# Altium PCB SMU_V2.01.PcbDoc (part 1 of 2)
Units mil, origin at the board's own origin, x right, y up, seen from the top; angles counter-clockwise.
Board outline 8661.42 x 7437.01 mil, 4 copper layers (Component Side, Ground Plane, Power Plane, Solder Side), stack 33.234 mil thick; 247 components, 163 nets, 805 pads, 762 vias.
Unrouted connection lines stored in the file: 6.
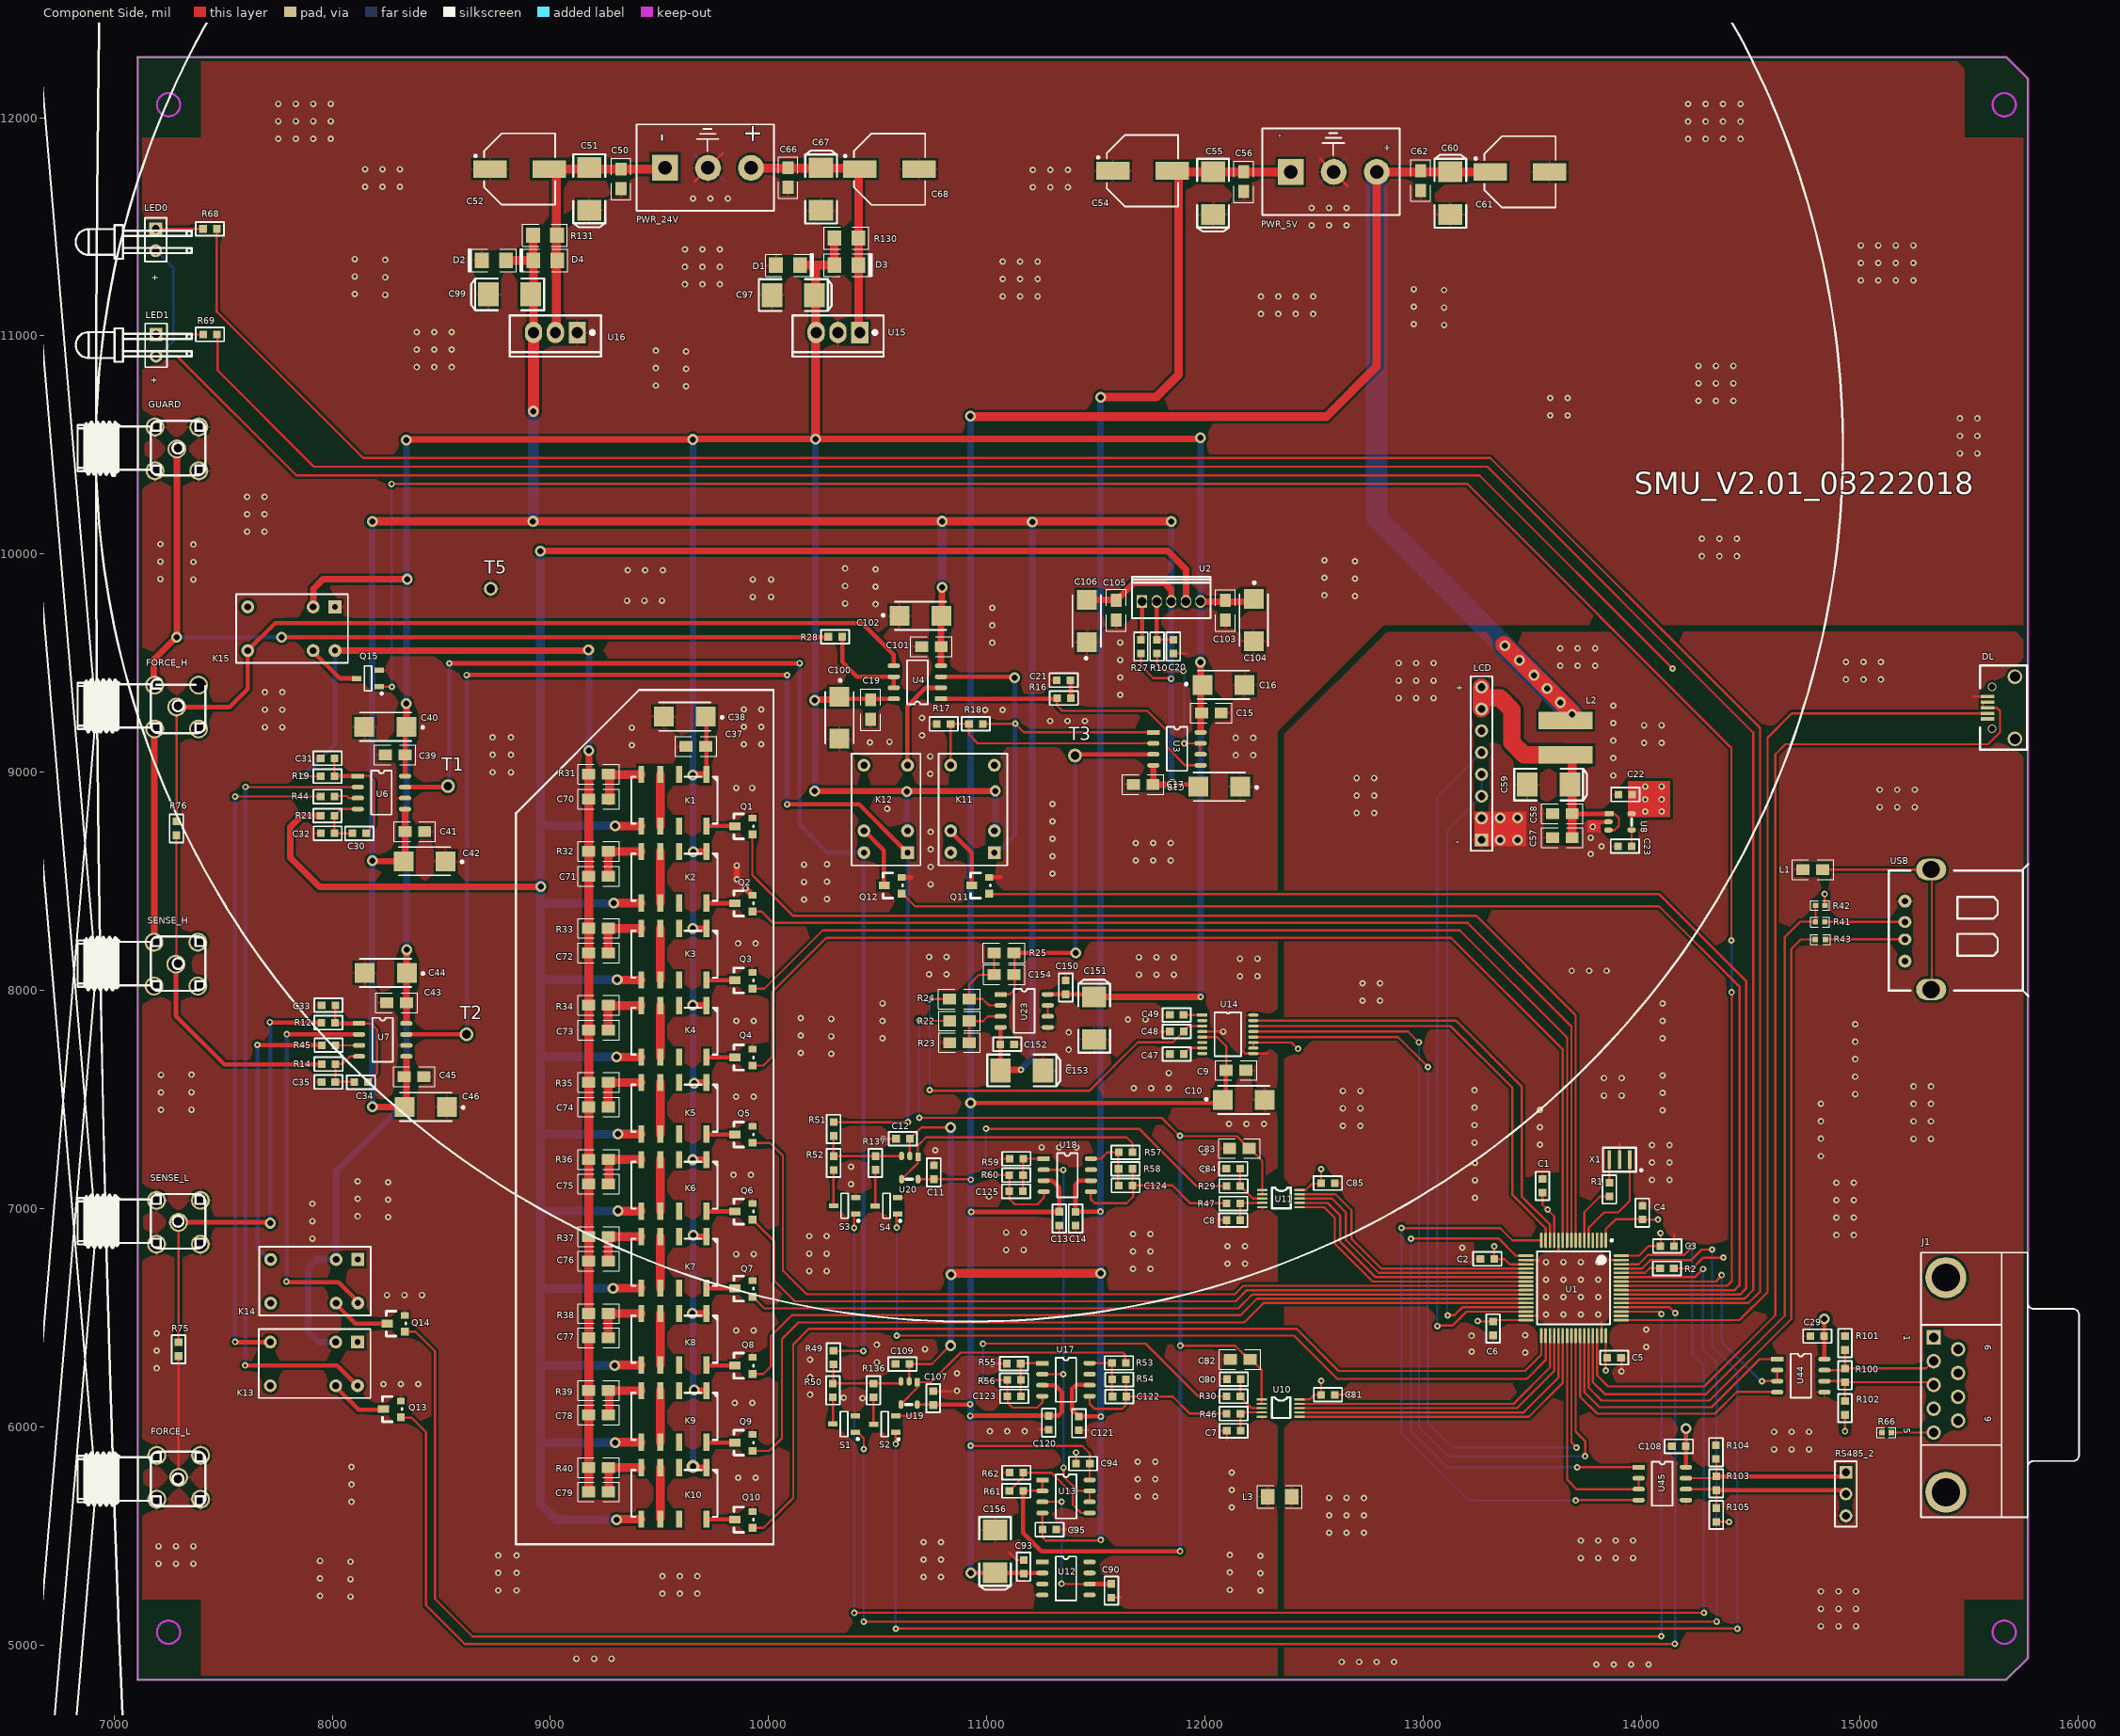
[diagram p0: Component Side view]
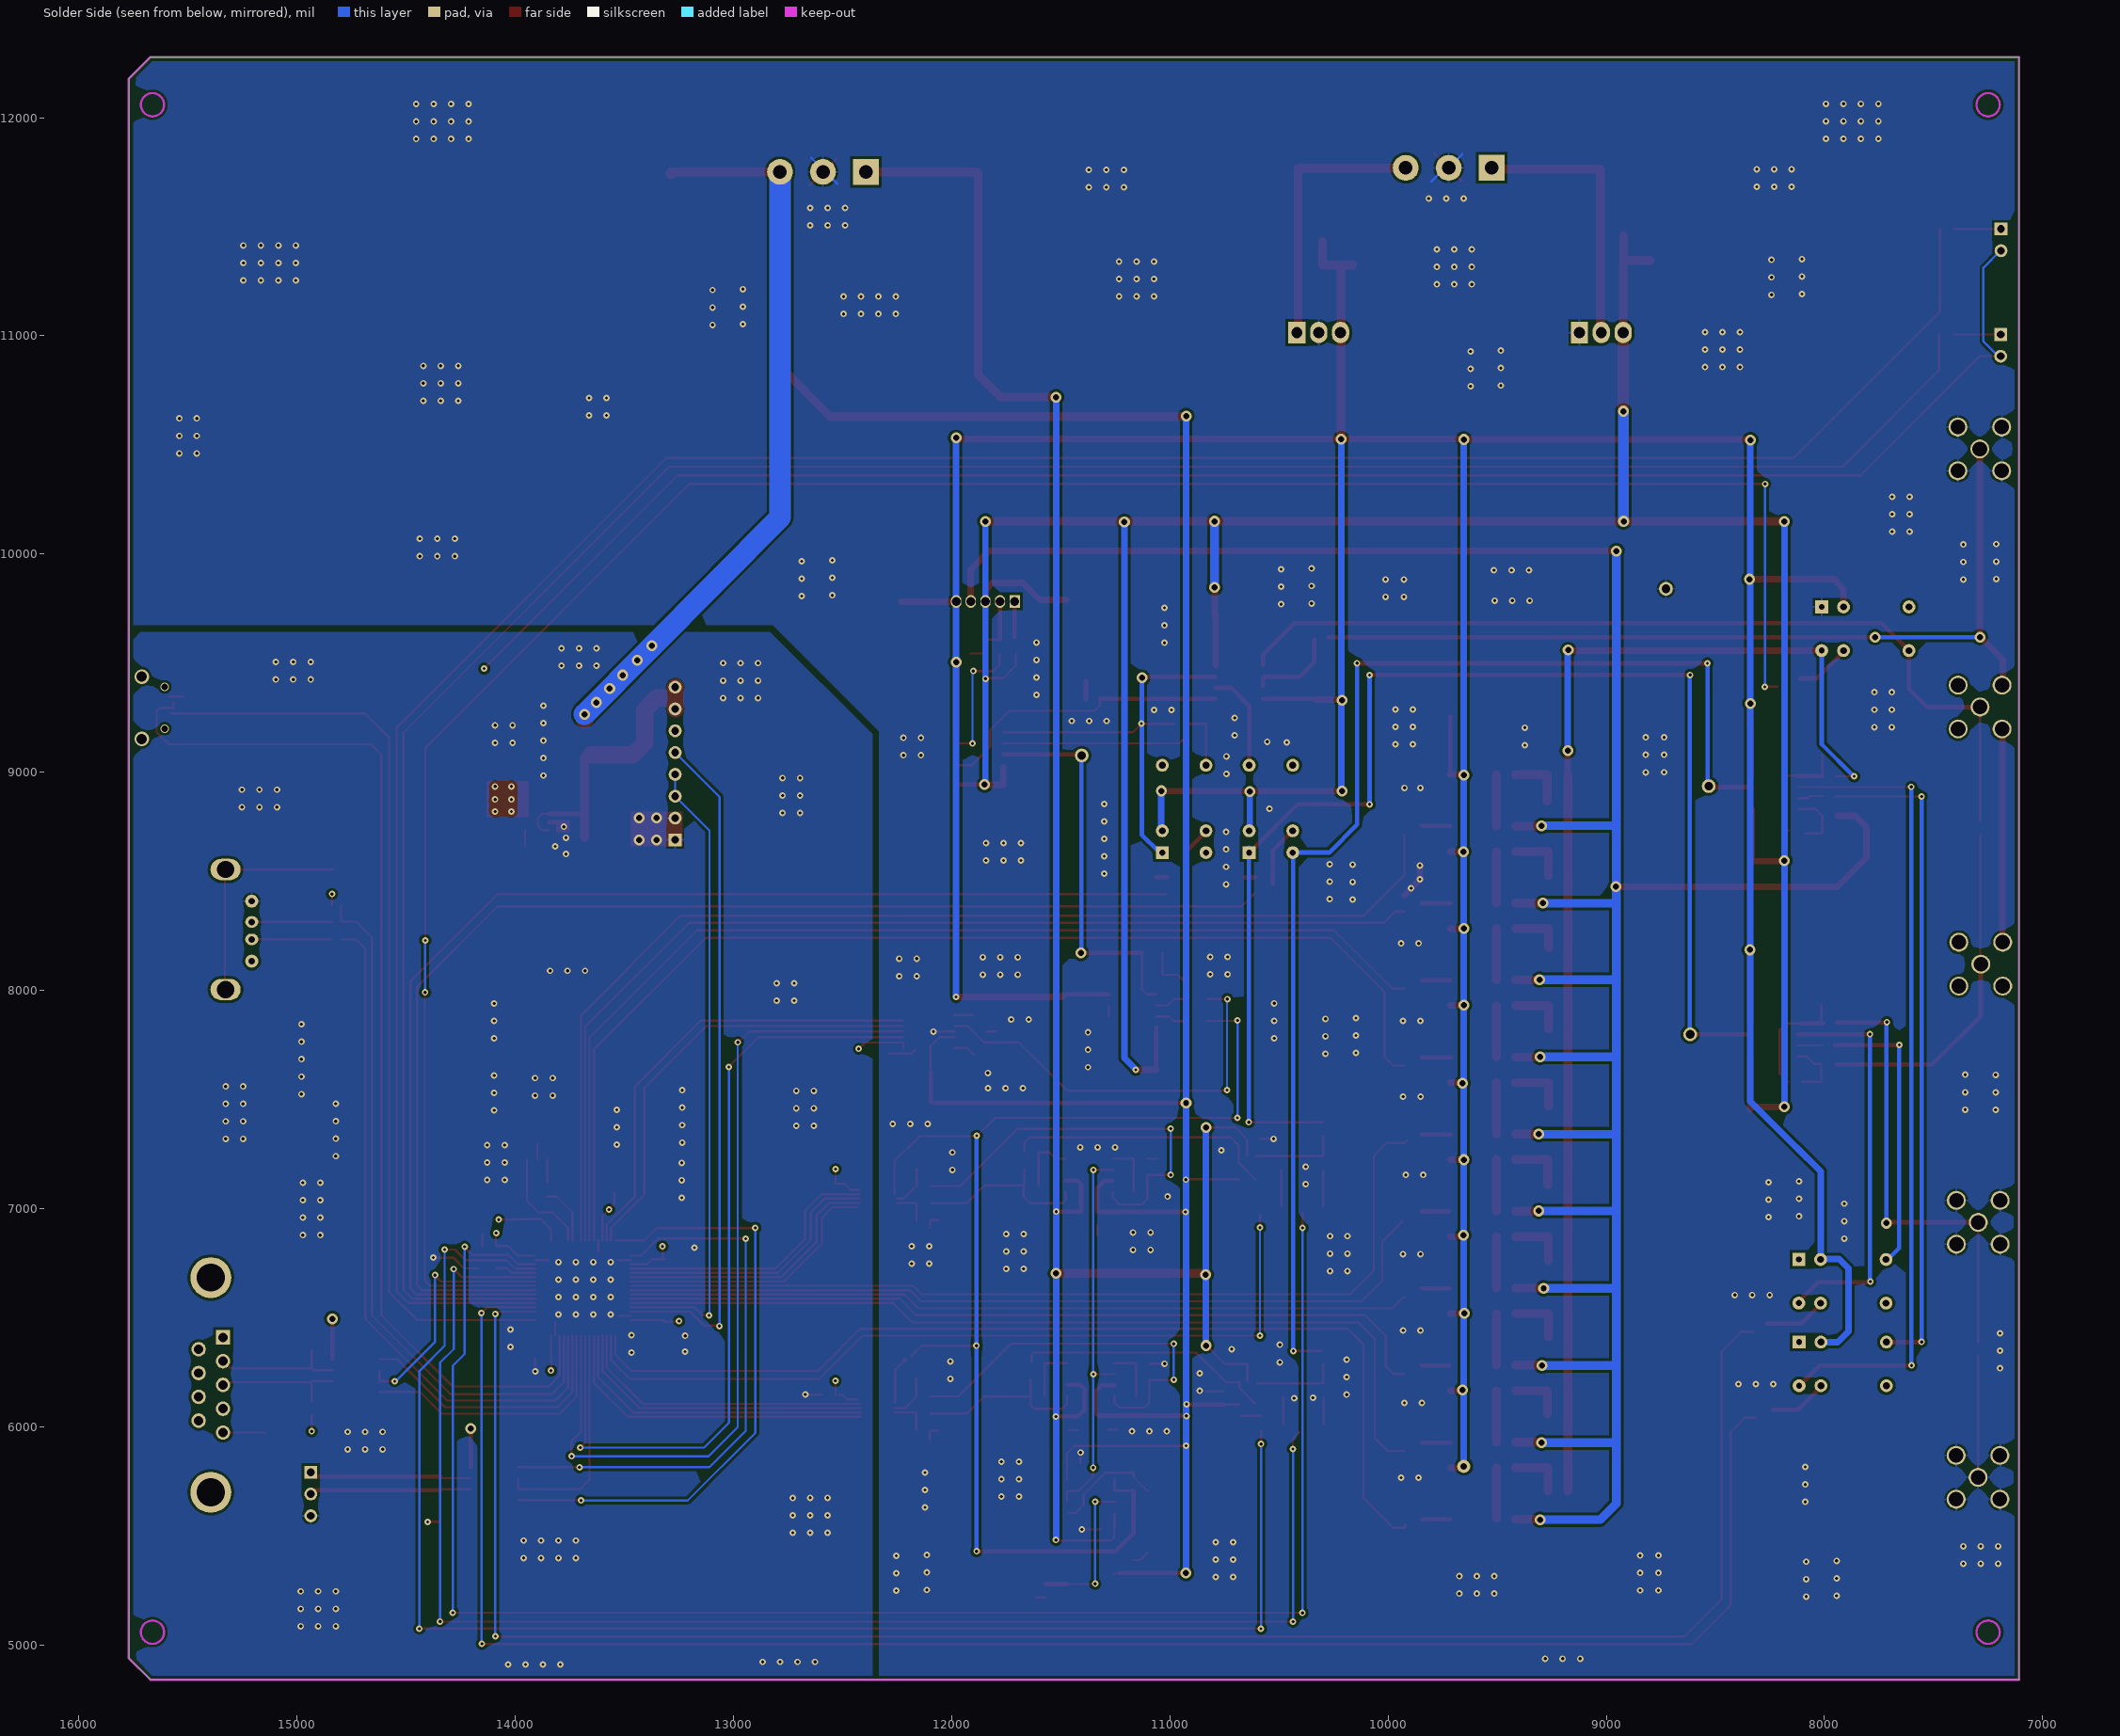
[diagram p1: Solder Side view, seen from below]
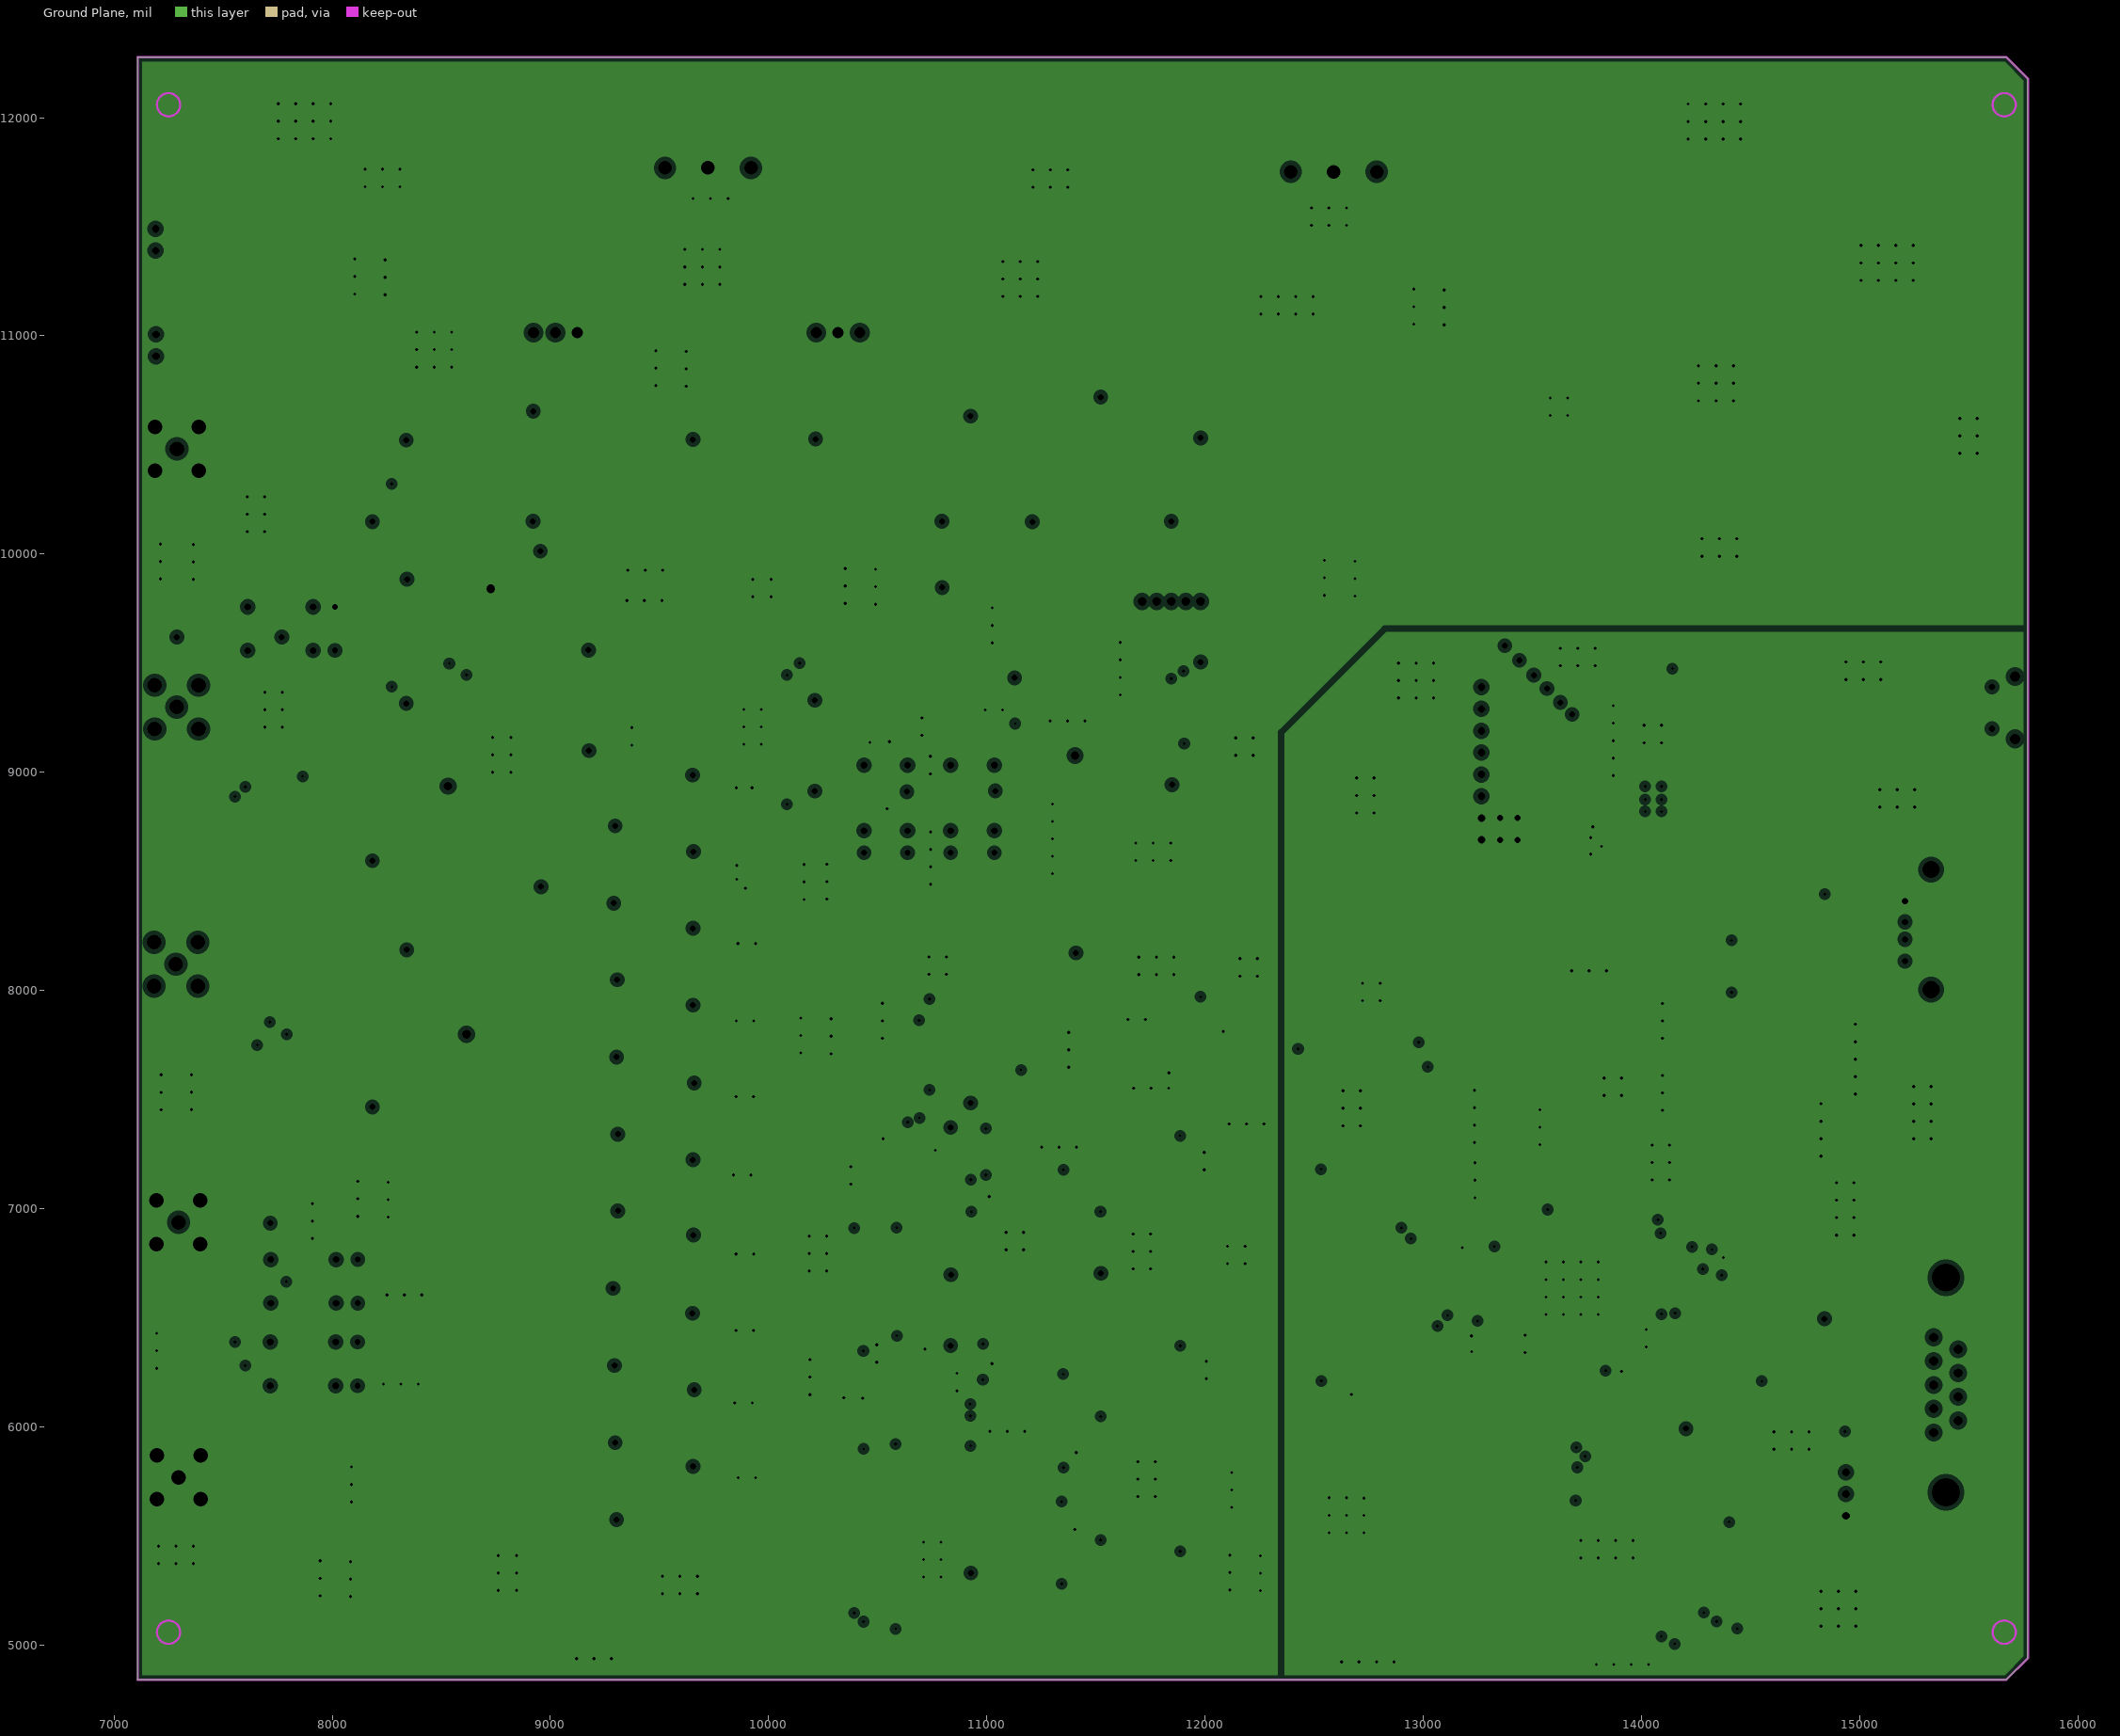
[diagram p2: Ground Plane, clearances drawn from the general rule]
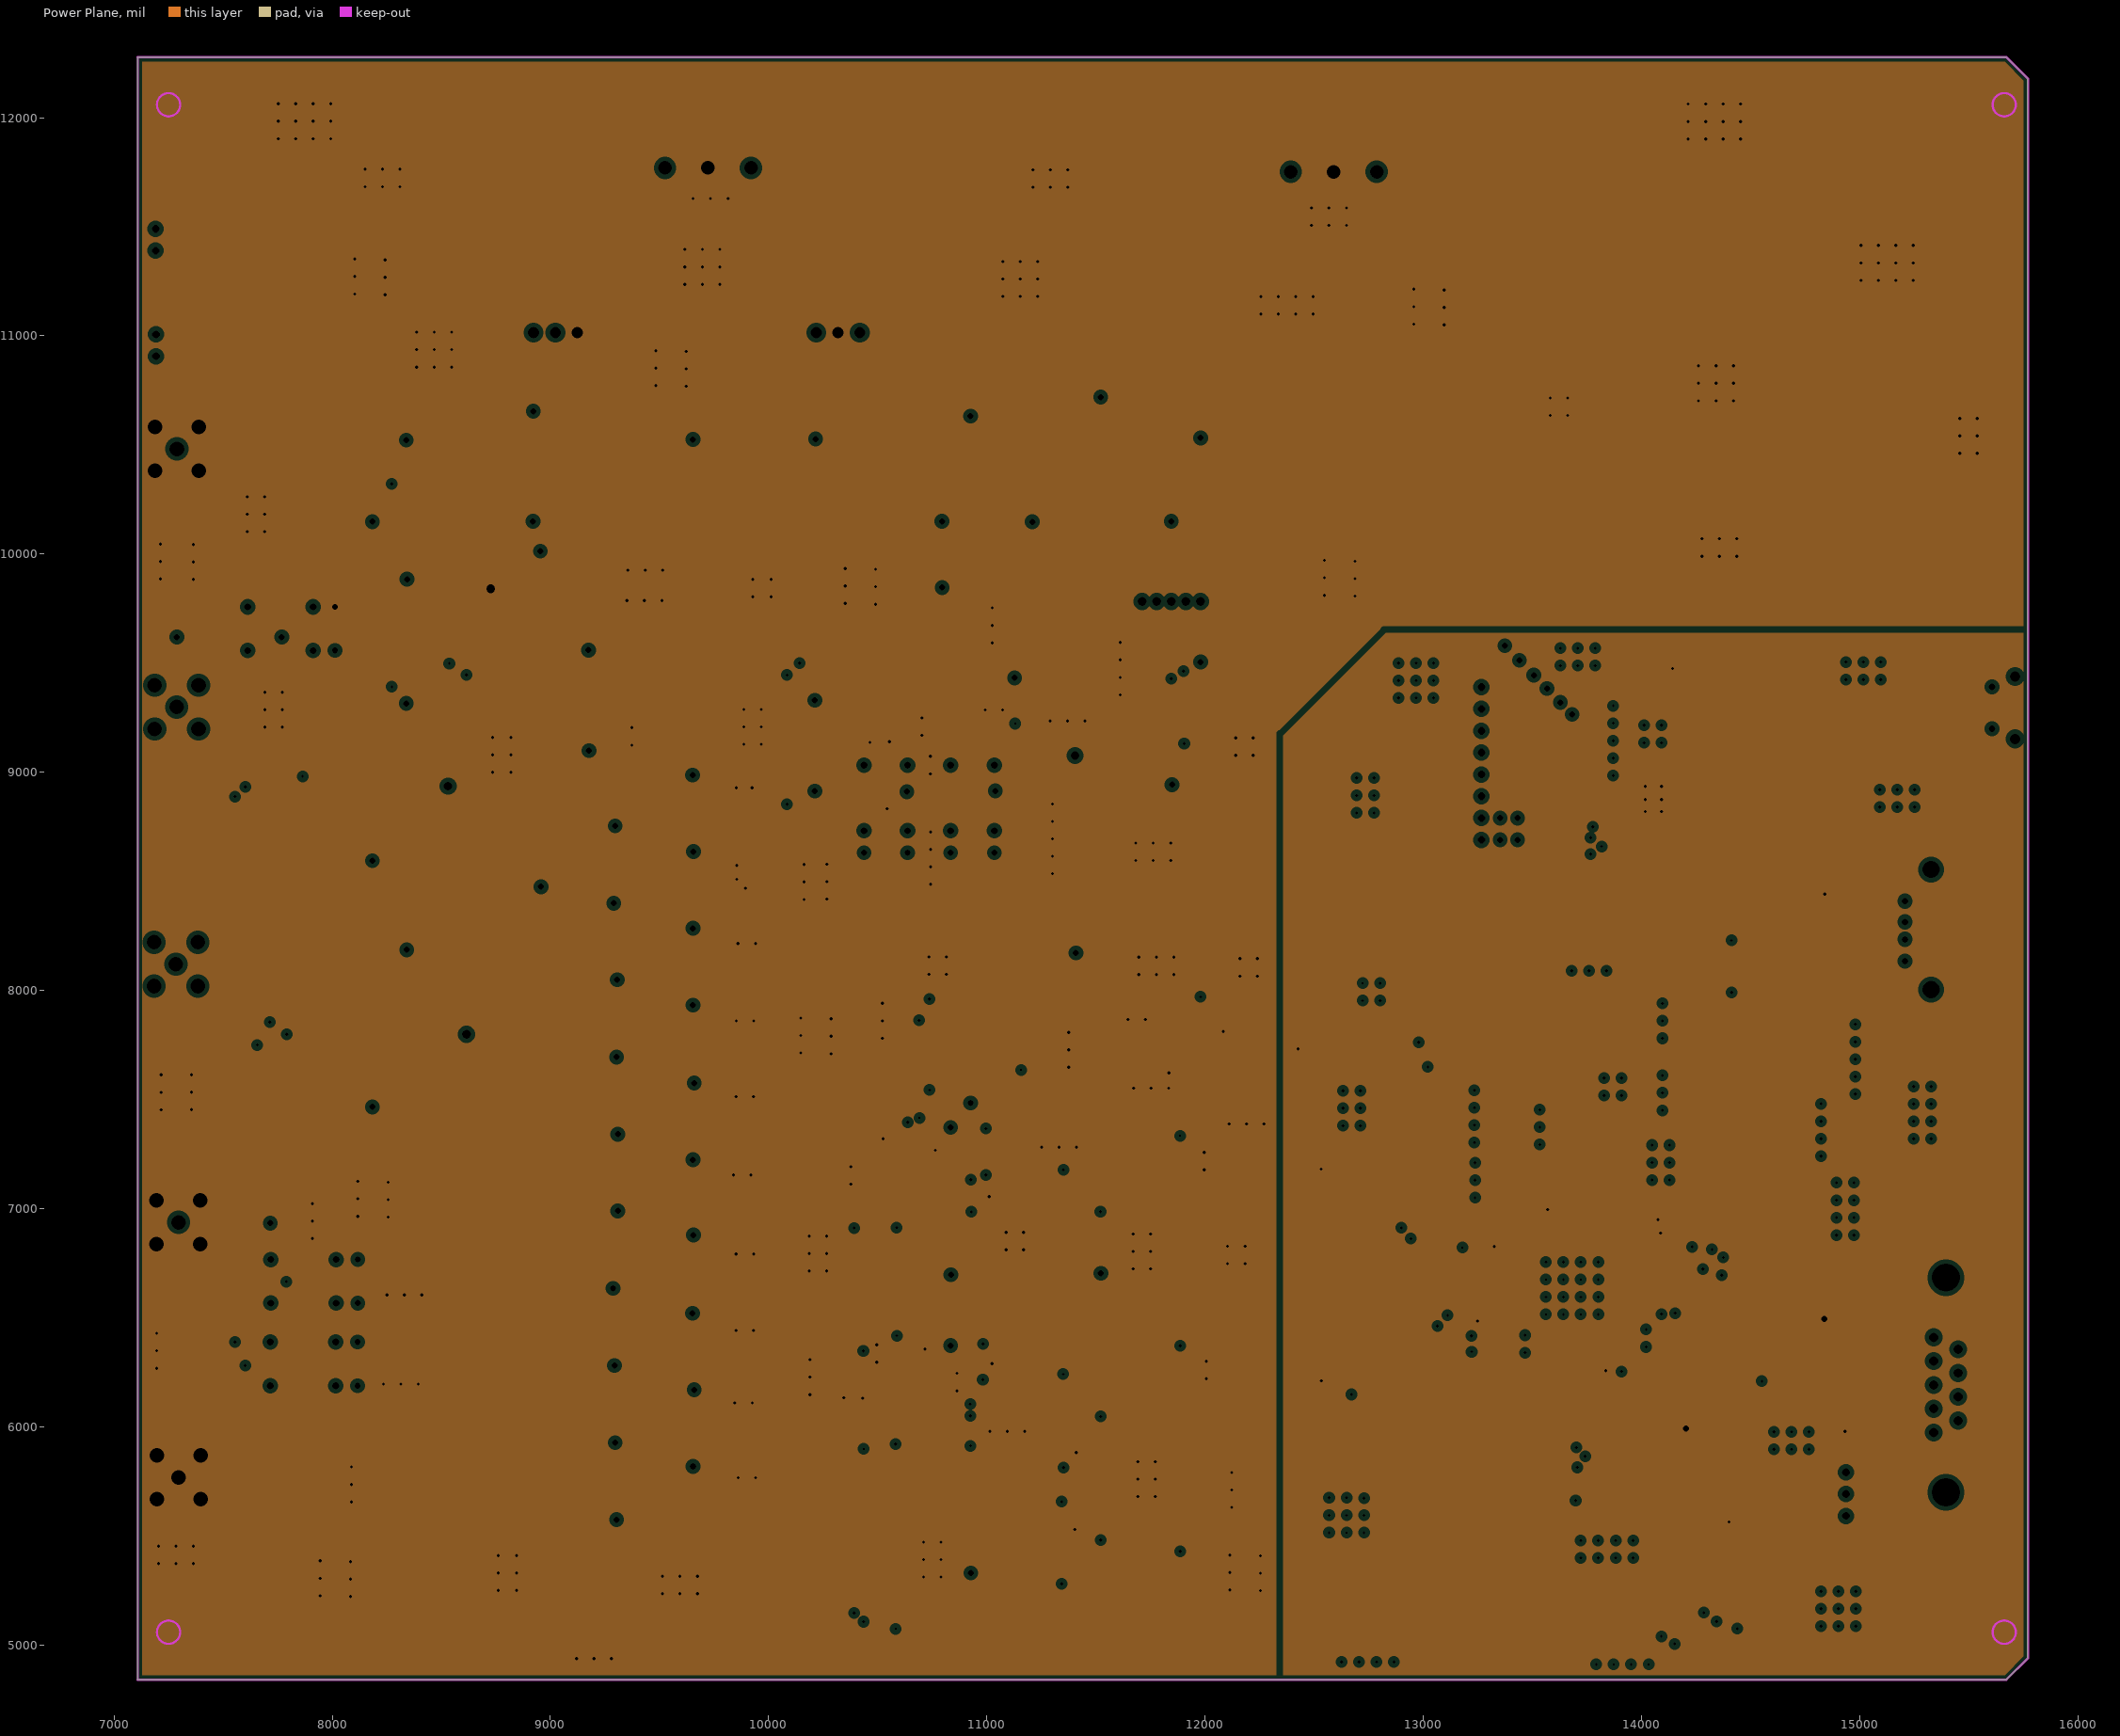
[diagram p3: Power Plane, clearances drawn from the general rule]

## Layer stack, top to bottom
Top Solder: solder mask 0.4, Solder Resist, Dk 3.5
Component Side: signal copper 1.4
Dielectric 1: core 12.6, FR-4, Dk 4.8
Ground Plane: plane copper 1.417, net (Multiple Nets)
Dielectric 3: prepreg 5, Dk 4.2
Power Plane: plane copper 1.417, net (Multiple Nets)
Dielectric 4: core 10, Dk 4.2
Solder Side: signal copper 1.4
Bottom Solder: solder mask 0.4, Solder Resist, Dk 3.5

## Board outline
7108.64,4840.98 15671.64,4840.98 15770.06,4939.41 15770.06,12179.56 15671.64,12277.99 7108.64,12277.99

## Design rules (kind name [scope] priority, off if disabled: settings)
Clearance [All] p1: gap=3
ComponentClearance [All] p1: gap=0 collisioncheckmode=3 verticalgap=0 showdistances=FALSE
MinimumSolderMaskSliver [All] p1: minsoldermaskwidth=0
PlaneClearance [All] p1: clearance=20
PlaneConnect PlaneConnect_GROUND [All] p1: planeconnectstyle=Relief reliefexpansion=20 reliefentries=4 reliefconductorwidth=10 reliefairgap=10
PlaneConnect "PlaneConnect _POWER" [All] p2: planeconnectstyle=Relief reliefexpansion=20 reliefentries=4 reliefconductorwidth=10 reliefairgap=10
PolygonConnect [IsVia] p1: connectstyle=Direct reliefconductorwidth=10 reliefentries=4 polygonreliefangle="90 Angle" airgapwidth=10
PolygonConnect PolygonConnect_1 [InNet('DGND')] p2: connectstyle=Relief reliefconductorwidth=10 reliefentries=4 polygonreliefangle="90 Angle" airgapwidth=10
PolygonConnect PolygonConnect_2 [InNet('AGND')] p3: connectstyle=Relief reliefconductorwidth=10 reliefentries=4 polygonreliefangle="90 Angle" airgapwidth=10
RoutingVias [All] p1: holewidth=28 width=50 viastyle="Through Hole" minholewidth=28 minwidth=50 maxholewidth=28 maxwidth=50
SilkToSilkClearance [All] p1: silktosilkclearance=0
SilkToSolderMaskClearance [IsPad] p1: minsilkscreentomaskgap=0 clearancetoexposedcopper=TRUE
SolderMaskExpansion [All] p1: expansion=4
UnpouredPolygon UnpouredPolygon_1 [All] p1:
Width [All] p1: maxlimit=100 minlimit=10 preferedwidth=10
23 further rules are at their usual default settings.

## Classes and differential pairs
component class Analog: C1 C2 C3 C4 C5 C6 C7 C8 C9 C10 C11 C12 C13 C14 C15 C16 C17 C18 C19 C20 C21 C22 C23 C29 C30 C31 C32 C33 C34 C35 C37 C38 C39 C40 C41 C42 C43 C44 C45 C46 C47 C48 C49 C57 C58 C59 C70 C71 C72 C73 C74 C75 C76 C77 C78 C79 C80 C81 C82 C83 C84 C85 C90 C93 C94 C95 C100 C101 C102 C103 C104 C105 C106 C107 C108 C109 C120 C121 C122 C123 C124 C125 C150 C151 C152 C153 C154 C156 DL FORCE_H FORCE_L GUARD J1 K1 K2 K3 K4 K5 K6 K7 K8 K9 K10 K11 K12 K13 K14 K15 L1 L3 LCD LED0 LED1 Q1 Q2 Q3 Q4 Q5 Q6 Q7 Q8 Q9 Q10 Q11 Q12 Q13 Q14 Q15 R1 R2 R10 R12 R14 R16 R17 R18 R19 R21 R22 R23 R24 R25 R27 R28 R29 R30 R31 R32 R33 R34 R35 R36 R37 R38 R39 R40 R41 R42 R43 R44 R45 R46 R47 R49 R50 R51 R52 R53 R54 R55 R56 R57 R58 R59 R60 R61 R62 R66 R68 R69 R75 R76 R100 R101 R102 R103 R104 R105 R136 R137 RS485_2 S1 S2 S3 S4 SENSE_H SENSE_L T1 T2 T3 T5 U1 U2 U3 U4 U6 U7 U8 U10 U11 U12 U13 U14 U17 U18 U19 U20 U23 U44 U45 USB X1
component class Power: C50 C51 C52 C54 C55 C56 C60 C61 C62 C66 C67 C68 C97 C99 D1 D2 D3 D4 L2 PWR_5V PWR_24V R130 R131 U15 U16

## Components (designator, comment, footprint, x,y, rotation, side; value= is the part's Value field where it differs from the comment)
C1 "100nF" 0603 13550.48,7043.53 r180 top
C2 "100nF" 0603 13354.54,6774.4 r270 top
C3 "100nF" 0603 14056.91,6824.38 r90 top
C4 "100nF" 0603 14008.06,6920.52 r180 top
C5 "100nF" 0603 13813.66,6312.96 r90 top
C6 "1uF" 0603 13315.34,6512.26 r0 top
C7 "22nF" 0603 12069.6,5978.17 r90 top
C8 "22nF" 0603 12068.37,6943.27 r90 top
C9 "100nF" 0805#1 12184.03,7609.44 r0 top
C10 "10uF" 6032_pol#1 12292.92,7453.09 r0 top
C11 "100nF" 0603 10760.95,7105.35 r180 top
C12 "100nF" 0603 10676.31,7324.54 r270 top
C13 "100nF" 0603 11327.81,7015.88 r0 top
C14 "100nF" 0603 11402.49,7015.82 r0 top
C15 "100nF" 0805#1 12070.49,9247.48 r0 top
C16 "10uF" 6032_pol#1 12200.77,9356.02 r0 top
C17 "100nF" 0805#1 11673.97,8969.84 r180 top
C18 "10uF" 6032_pol#1 11949.27,8978.82 r180 top
C19 "100nF" 0805#1 10441.9,9245.11 r270 top
C20 "1uF" 0603 11850.08,9637.47 r0 top
C21 "3.3nF" 0603 11290.55,9417.61 r90 top
C22 "1uF" 0603 13987.23,8902.48 r270 top
C23 "22nF" 0603 13985.05,8665.49 r270 top
C29 "100nF" 0603 14866.88,6420.31 r270 top
C30 "10nF" 0603 8063.17,8716 r90 top
C31 "1nF" 0603 8039.71,9068.37 r270 top
C32 "1nF" 0603 7918.07,8716.26 r90 top
C33 "1nF" 0603 8043.66,7936.76 r270 top
C34 "10nF" 0603 8070.53,7575.3 r90 top
C35 "1nF" 0603 7921.06,7576.63 r90 top
C37 "100nF" 0805#1 9624.82,9143.09 r180 top
C38 "10uF" 6032_pol#1 9499.21,9300.12 r180 top
C39 "100nF" 0805#2 8333.18,9079.96 r180 top
C40 "10uF" 6032_pol#1 8127.6,9253.9 r180 top
C41 "100nF" 0805#2 8333.18,8727.7 r0 top
C42 "10uF" 6032_pol#1 8307.8,8637.61 r180 top
C43 "100nF" 0805#1 8252.87,7968.98 r180 top
C44 "10uF" 6032_pol#1 8128.97,8125.71 r180 top
C45 "100nF" 0805#1 8417.16,7580.34 r0 top
C46 "10uF" 6032_pol#1 8312.48,7511.95 r180 top
C47 "100nF" 0603 11808.82,7704.57 r90 top
C48 "100nF" 0603 11808.73,7807.87 r90 top
C49 "100nF" 0603 11808.57,7883.63 r90 top
C50 "100nF" 0805#2 9323.53,11674.48 r90 top
C51 "10uF" 6032_POL 9179.33,11676.39 r270 top
C52 "47uF" cap_pol_8*10.2#1 8858.53,11764.48 r0 top
C54 "47uF,50V" cap_pol_8*10.2#1 11712.82,11756.73 r0 top
C55 "10uF" 6032_POL 12037.82,11656.73 r270 top
C56 "1uF" 0805#2 12177.82,11751.73 r270 top
C57 "100nF" 0805#2 13681.88,8700.31 r180 top
C58 "1uF" 0805#2 13681.88,8810.31 r180 top
C59 "10uF" 6032_POL 13571.88,8945.31 r0 top
C60 "10uF" 6032_POL 13122.82,11651.73 r90 top
C61 "47uF,50V" cap_pol_8*10.2#1 13442.82,11751.73 r0 top
C62 "1uF" 0805#2 12987.82,11756.73 r270 top
C66 "100nF" 0805#2 10088.88,11680.76 r90 top
C67 "10uF" 6032_pol#2 10238.3,11670.99 r90 top
C68 "47uF" cap_pol_8*10.2#2 10553.42,11764.23 r90 top
C70 "10uF" 0805#1 9178.42,8902.04 r180 top
C71 "1uF" 0805#1 9178.42,8549.31 r180 top
C72 "100nF" 0805#1 9178.42,8196.58 r180 top
C73 "10nF" 0805#1 9178.42,7843.86 r180 top
C74 "1nF" 0805#1 9178.42,7491.13 r180 top
C75 "100pF" 0805#1 9178.42,7138.4 r180 top
C76 "10pF" 0805#1 9178.42,6785.67 r180 top
C77 "1pF" 0805#2 9265.42,6407.94 r180 top
C78 "NULL" 0805#1 9178.42,6080.22 r180 top
C79 "NULL" 0805#1 9178.42,5727.49 r180 top
C80 "22nF" 0603 12070.8,6214.57 r90 top
C81 "100nF" 0603 12501.95,6142.99 r90 top
C82 "10uF" 0805#2 12115.37,6309.11 r0 top
C83 "10uF" 0805#2 12112.28,7276.4 r0 top
C84 "22nF" 0603 12190.12,7187.39 r270 top
C85 "100nF" 0603 12501.73,7112.73 r90 top
C90 "100nF" 0603 11566.02,5310.6 r0 top
C93 "100nF" 0603 11164.02,5419.82 r0 top
C94 "100nF" 0603 11501.73,5835.91 r270 top
C95 "100nF" 0603 11225.8,5525.27 r90 top
C97 "4.7uF" 6032_pol#2 10110.36,11188.68 r0 top
C99 "4.7uF" 6032_pol#2 8814.93,11188.34 r180 top
C100 "10uF" 6032_pol#1 10279.34,9133.91 r270 top
C101 "100nF" 0805#1 10703.53,9600.98 r180 top
C102 "10uF" 6032_pol#1 10811.76,9671.85 r0 top
C103 "100nF" 0805#1 12068.6,9700.4 r270 top
C104 "10uF" 6032_pol#1 12177.51,9581.71 r270 top
C105 "100nF" 0805#1 11568.47,9700.93 r270 top
C106 "10uF" 6032_pol#1 11502.57,9809.31 r90 top
C107 "100nF" 0603 10758.22,6070.24 r180 top
C108 "100nF" 0603 14231.88,5915.31 r270 top
C109 "100nF" 0603 10674.38,6292.32 r270 top
C120 "100nF" 0603 11279.16,6080.54 r0 top
C121 "100nF" 0603 11417.42,6077.73 r0 top
C122 "100pF" 0603 11545.94,6134.74 r90 top
C123 "100pF" 0603 11186.51,6144.43 r270 top
C124 "100pF" 0603 11574.9,7102.1 r90 top
C125 "100pF" 0603 11195.13,7083.88 r270 top
C150 "100nF" 0603 11365.84,7952.81 r180 top
C151 "10uF" 6032_pol#2 11490.03,7870.86 r90 top
C152 "100nF" 0603 11032.3,7749.28 r90 top
C153 "10uF" 6032_pol#2 11157.57,7635.09 r0 top
C154 "100pF" 0805#2 11124.08,8072.24 r180 top
C156 "10uF" 6032_pol#2 11039.23,5431.95 r270 top
D1 "1N4007" 1N4007_M7 10085.74,11310.46 r0 top
D2 "1N4007" 1N4007_M7 8742.68,11359.59 r180 top
D3 "Diode 1N4007" 1N4007_M7 10353.38,11310.75 r0 top
D4 "Diode 1N4007" 1N4007_M7 8979.22,11359.85 r180 top
DL "USB_5pin" USBmicro_B 15691,9305.31 r270 top
FORCE_H "SMB" SMA 7186.47,9399.39 r0 top
FORCE_L "SMB" SMA 7195.73,5869.31 r0 top
GUARD "SMB" SMA 7187.68,10582.57 r0 top
J1 "USART" DSUB1.385-2H9 15768.88,6192.26 r270 top
K1 "AXICOM IM" AXICOM_IM06 9590.6,8865 r180 top
K2 "AXICOM IM" AXICOM_IM06 9590.6,8512.03 r180 top
K3 "AXICOM IM" AXICOM_IM06 9590.6,8159.06 r180 top
K4 "AXICOM IM" AXICOM_IM06 9590.6,7806.09 r180 top
K5 "AXICOM IM" AXICOM_IM06 9590.6,7453.12 r180 top
K6 "AXICOM IM" AXICOM_IM06 9590.6,7100.15 r180 top
K7 "AXICOM IM" AXICOM_IM06 9590.6,6747.18 r180 top
K8 "AXICOM IM" AXICOM_IM06 9590.6,6394.2 r180 top
K9 "AXICOM IM" AXICOM_IM06 9590.6,6041.23 r180 top
K10 "AXICOM IM" AXICOM_IM06 9590.6,5688.26 r180 top
K11 "Relay" Relay_OMRON5V 11034.46,8632.05 r180 top
K12 "Relay" Relay_OMRON5V 10636.55,8632.05 r180 top
K13 "Relay" Relay_OMRON5V 8116.11,6388.63 r270 top
K14 "Relay" Relay_OMRON5V 8117.56,6767.3 r270 top
K15 "Relay" Relay_OMRON5V 8012.65,9757.88 r270 top
L1 "10uH" 0805#2 14740.19,8554.29 r0 top
L2 "10uH" 8040 13651.88,9080.31 r0 top
L3 "10uH" 1206 12286.48,5679.69 r0 top
LCD "Header 8" HDR1X8 13266.88,8690.31 r90 top
LED0 "Header 2" HDR1X2 7190.85,11490.63 r270 top
LED1 "Header 2" HDR1X2 7192.45,11006.75 r270 top
PWR_5V "Header 3" PWR_3T 12392.82,11751.73 r90 top
PWR_24V "Header 3" PWR_3T 9525.2,11770.04 r90 top
Q1 "NUD3112" SOT_23 9925.06,8722.04 r0 top
Q2 "NUD3112" SOT_23 9925.06,8368.95 r0 top
Q3 "NUD3112" SOT_23 9925.06,8015.87 r0 top
Q4 "NUD3112" SOT_23 9925.06,7662.79 r0 top
Q5 "NUD3112" SOT_23 9925.06,7309.7 r0 top
Q6 "NUD3112" SOT_23 9925.06,6956.62 r0 top
Q7 "NUD3112" SOT_23 9925.06,6603.54 r0 top
Q8 "NUD3112" SOT_23 9925.06,6250.45 r0 top
Q9 "NUD3112" SOT_23 9925.06,5897.37 r0 top
Q10 "NUD3112" SOT_23 9925.06,5544.29 r0 top
Q11 "NUD3112" SOT_23 11010.38,8451.12 r0 top
Q12 "NUD3112" SOT_23 10608.7,8450.55 r0 top
Q13 "NUD3112" SOT_23 8314.41,6051.05 r0 top
Q14 "NUD3112" SOT_23 8331.76,6443.14 r0 top
Q15 "NUD3112" SOT23 8162.78,9432.23 r180 top
R1 "100R" 0603 13857.39,7026.81 r180 top
R2 "10K" 0603 14177.75,6730.52 r270 top
R10 "1M" 0603 11775.51,9637.29 r0 top
R12 "2.2K,0.1%" 0603 8043.03,7856.6 r270 top
R14 "2.2K,0.1%" 0603 8044.09,7666.99 r270 top
R16 "100K" 0603 11414.2,9344.52 r270 top
R17 "1K，0.1%" 0603 10740.84,9217.44 r90 top
R18 "4.99K" 0603 10888.21,9217.6 r90 top
R19 "2.2K,0.1%" 0603 7917.24,8978.06 r90 top
R21 "2.2K,0.1%" 0603 7917.08,8797.24 r90 top
R22 "5.1K" 0805#2 10919.65,7860.77 r180 top
R23 "5.1K" 0805#2 10919.43,7761.25 r180 top
R24 "5.1K" 0805#2 10918.57,7960.42 r180 top
R25 "5.1K" 0805#2 11123.61,8172.08 r180 top
R27 "100R" 0603 11701.7,9637.38 r0 top
R28 "1K" 0603 10243.49,9616.95 r90 top
R29 "1K" 0603 12190.91,7108.11 r270 top
R30 "1K" 0603 12191.86,6144.51 r270 top
R31 "1R" 0805#1 9178.42,9016.57 r180 top
R32 "10R" 0805#1 9178.42,8663.41 r180 top
R33 "100R" 0805#1 9178.42,8310.25 r180 top
R34 "1K" 0805#2 9265.42,7932.09 r180 top
R35 "10K" 0805#2 9265.42,7578.92 r180 top
R36 "100K" 0805#2 9265.42,7225.76 r180 top
R37 "1M" 0805#2 9265.42,6872.6 r180 top
R38 "10M" 0805#1 9178.42,6544.44 r180 top
R39 "100M" 0805#1 9178.42,6191.28 r180 top
R40 "1G" 0805#1 9178.42,5838.12 r180 top
R41 "22R" 0402#1 14711.88,8310.31 r90 top
R42 "1.5K" 0402#1 14712.71,8385.9 r90 top
R43 "22R" 0402#2 14715.42,8230.07 r90 top
R44 "2.2K, 0.1%" 0603 8039.43,8893.2 r270 top
R45 "2.2K, 0.1%" 0603 8044.36,7753.56 r270 top
R46 "1K" 0603 12191.6,6064.92 r270 top
R47 "1K" 0603 12190.69,7028.01 r270 top
R49 "2.2K" 0603 10292.47,6379.74 r0 top
R50 "9.1K" 0603 10290.18,6228.63 r0 top
R51 "2.2K" 0603 10293.3,7426.19 r0 top
R52 "9.1K" 0603 10293.3,7270.56 r0 top
R53 "1K, 0.1%" 0603 11666.16,6297.48 r270 top
R54 "1K, 0.1%" 0603 11667.46,6221.61 r270 top
R55 "1K, 0.1%" 0603 11185.03,6294.1 r270 top
R56 "1K, 0.1%" 0603 11063.56,6210.45 r90 top
R57 "1K, 0.1%" 0603 11696.57,7262.6 r270 top
R58 "1K, 0.1%" 0603 11696.53,7186.54 r270 top
R59 "1K, 0.1%" 0603 11074.02,7224.67 r90 top
R60 "1K, 0.1%" 0603 11073.19,7149.67 r90 top
R61 "10K, 0.1%" 0603 11073.38,5702.93 r90 top
R62 "10K, 0.1%" 0603 11074.01,5786.11 r90 top
R66 "0R" 0402#1 15229.34,5977.95 r270 top
R68 "510R" 0603 7500.39,11494.56 r270 top
R69 "510R" 0603 7500.82,11010.87 r270 top
R75 "1K，0.1%" 0603 7299.63,6294.45 r180 top
R76 "1K，0.1%" 0603 7290.15,8681.28 r180 top
R100 "NULL" 0603 14936.88,6175.31 r180 top
R101 "NULL" 0603 14928.38,6445.31 r0 top
R102 "NULL" 0603 14936.88,6025.31 r180 top
R103 "NULL" 0603 14346.88,5680.31 r180 top
R104 "NULL" 0603 14336.88,5945.31 r0 top
R105 "NULL" 0603 14346.88,5535.31 r180 top
R130 "0R" 1206 10410.97,11448.55 r180 top
R131 "0R" 1206 9030.29,11461.48 r180 top
R136 "2.2K" 0603 10475.91,6228.44 r0 top
R137 "2.2K" 0603 10484.92,7270.76 r0 top
RS485_2 "Header 3" HDR1X3 14936.81,5792.26 r270 top
S1 "SI2302CDS" SOT23 10344.41,6014.97 r180 top
S2 "SI2302CDS" SOT23 10530.89,6014.52 r180 top
S3 "SI2302CDS" SOT23 10347.39,7015.24 r180 top
S4 "SI2302CDS" SOT23 10538.84,7015.23 r180 top
SENSE_H "SMB" SMA 7183.17,8220.98 r0 top
SENSE_L "SMB" SMA 7194.97,7038 r0 top
T1 "TestPoint" TestPoint 8530.43,8936.64 r0 top
T2 "TestPoint" TestPoint 8615.51,7799.05 r0 top
T3 "TestPoint" TestPoint 11404.11,9076.96 r0 top
T5 "TestPoint" TestPoint 8726.33,9841.28 r0 top
U1 "STM32F103RET6" LQFP64_N 13681.88,6635.31 r90 top
U2 "BUF634" PSFM-T5 11711.2,9782.7 r90 top
U3 "AD4522-2" SO-8N#1 11920.79,9053.11 r0 top
U4 "AD4522-2" SO-8N#1 10631.97,9466.99 r180 top
U6 "AD8422ARZ" SO-8N#1 8275.1,8852.5 r0 top
U7 "AD8422ARZ" SO-8N#1 8281.04,7719.28 r0 top
U8 "RT9193" SOT-23-5 13895.71,8771.26 r270 top
U10 "AD7988-1" MSOP10 12355.83,6053.59 r0 top
U11 "AD7988-1" MSOP10 12357.02,7013.81 r0 top
U12 "ADR441" SO-8N#1 11412.01,5250.81 r0 top
U13 "AD8676" SO-8N#2 11254.6,5756.83 r0 top
U14 "AD5689R" TSSOP16 11988.04,7888.42 r0 top
U15 "7815" TO-220 10316.64,11015.51 r180 top
U16 "7915" TO-220 9021.53,11015.51 r180 top
U17 "AD8137" SO-8N#1 11412.04,6161.99 r0 top
U18 "AD8137" SO-8N#1 11418.38,7098.99 r0 top
U19 "ADA4000-1" SOT-23-5 10641.97,6161.38 r180 top
U20 "ADA4000-1" SOT-23-5 10644.93,7194.23 r180 top
U23 "AD8676" SO-8N#2 11062.71,7982.31 r0 top
U44 "SP3485" SO-8N#2 14621.88,6310.31 r0 top
U45 "SP3485" SO-8N#2 13986.88,5815.31 r0 top
USB "USB" USB_A 15415.03,8315.31 r0 top
X1 "8M smd" 8Mhz_XTAL 13946.36,7225.16 r180 top

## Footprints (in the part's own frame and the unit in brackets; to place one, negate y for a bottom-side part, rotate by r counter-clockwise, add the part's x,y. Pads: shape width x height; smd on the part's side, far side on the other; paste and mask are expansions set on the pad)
1N4007_M7 [mm]
  rect 1.6x1.8 smd: 1(-1.34,0.34) 2(1.46,0.34)
  silkscreen extent -2.54,-0.96 2.99,1.64
8Mhz_XTAL [mm]
  rect 0.4x2.2 smd: 1(0,0) 2(1.2,0) 3(2.4,0)
  silkscreen extent -1.45,-1.39 3.13,1.4
0402#1 [mil]
  rect 25x25 smd: 1(3.98,-127.99) 2(3.98,-84.98)
  silkscreen extent -19,-150 26,-63
0402#2 [mil]
  rect 25x25 smd: 1(4.06,-127.99) 2(4.06,-80.75)
  silkscreen extent -19,-150 26,-59
0603 [mil]
  rect 35x35 smd: 1(4.25,-92.76) 2(4.25,-29.76)
  silkscreen extent -27,-126 36,4
0805#1 [mil]
  rect 60x50 smd: 1(3,25) 2(-87,25)
  silkscreen extent -137,-20 53,70
0805#2 [mil]
  rect 60x50 smd: 1(90,0) 2(0,0)
  silkscreen extent -50,-45 140,45
1206 [mm]
  rect 1.6x1.8 smd: 1(0,0) 2(2.8,0)
  silkscreen extent -1.2,-1.3 4,1.3
6032_pol#1 [mm]
  rect 2.3x2.3 smd: 1(-5.396,1.143) 2(-0.496,1.143)
  silkscreen extent -7.43,-0.51 0.05,2.79
6032_pol#2 [mm]
  rect 2.4x2.8 smd: 1(2.538,-0.041) 2(-2.422,-0.041)
  silkscreen extent -3.95,-1.89 4.53,1.81
6032_POL [mm]
  rect 2.4x2.8 smd: 1(2.538,-0.041) 2(-2.422,-0.041)
  silkscreen extent -3.95,-1.89 4.53,1.81
8040 [mm]
  rect 6.3x2 smd: 1(0,4) 2(0,0)
AXICOM_IM06 [mm]
  rect 0.7x2 smd: 1(-3.174,-3.174) 2(0.026,-3.174) 3(2.226,-3.174) 4(4.426,-3.174) 5(4.426,2.826) 6(2.226,2.826) 7(0.026,2.826) 8(-3.174,2.826)
  silkscreen extent -4.44,-2.92 5.59,2.54
cap_pol_8*10.2#1 [mm]
  rect 3.9x2.05 smd: 1(-3.443,-0.001) 2(3.457,-0.001)
  silkscreen extent -5.27,-4.15 4.16,4.15
cap_pol_8*10.2#2 [mm]
  rect 2.05x3.9 smd: 1(-0.001,3.443) 1(-0.001,3.443) 2(-0.001,-3.457) 2(-0.001,-3.457)
  silkscreen extent -4.15,-4.16 4.15,5.27
DSUB1.385-2H9 [mm] "Connector; D Subminiature; 9 Position; Right Angle; Pitch 1.385 mm"
  rect 1.69x1.69 hole 1.09: 1(-5.54,-10.92)
  round 1.69 hole 1.09: 2(-2.77,-10.92) 3(0,-10.92) 4(2.77,-10.92) 5(5.54,-10.92) 6(-4.155,-8.08) 7(-1.385,-8.08) 8(1.385,-8.08) 9(4.155,-8.08)
  round 4.76 hole 3.26: 10(-12.495,-9.5) 11(12.495,-9.5)
  silkscreen extent -15.4,-12.4 15.4,6
HDR1X2 [mm] "Connector; Header; 2 Position"
  rect 1.5x1.5 hole 0.9: 1(0,0)
  round 1.5 hole 0.9: 2(2.54,0)
  silkscreen extent -1.27,-1.27 3.81,1.27
HDR1X3 [mm] "Connector; Header; 3 Position"
  rect 1.5x1.5 hole 0.9: 1(0,0)
  round 1.5 hole 0.9: 2(2.54,0) 3(5.08,0)
  silkscreen extent -1.27,-1.27 6.35,1.27
HDR1X8 [mm] "Connector; Header; 8 Position"
  rect 1.5x1.5 hole 0.9: 1(0,0)
  round 1.5 hole 0.9: 2(2.54,0) 3(5.08,0) 4(7.62,0) 5(10.16,0) 6(12.7,0) 7(15.24,0) 8(17.78,0)
  silkscreen extent -1.27,-1.27 19.05,1.27
LQFP64_N [mm]
  oval 1.8x0.3 smd: 1(5.586,-3.921) 2(5.586,-3.421) 3(5.586,-2.921) 4(5.586,-2.421) 5(5.586,-1.921) 6(5.586,-1.421) 7(5.586,-0.921) 8(5.586,-0.421) 9(5.586,0.079) 10(5.586,0.579) 11(5.586,1.079) 12(5.586,1.579) 13(5.586,2.079) 14(5.586,2.579) 15(5.586,3.079) 16(5.586,3.579) 33(-5.514,3.579) 34(-5.514,3.079) 35(-5.514,2.579) 36(-5.514,2.079) 37(-5.514,1.579) 38(-5.514,1.079) 39(-5.514,0.579) 40(-5.514,0.079) 41(-5.514,-0.421) 42(-5.514,-0.921) 43(-5.514,-1.421) 44(-5.514,-1.921) 45(-5.514,-2.421) 46(-5.514,-2.921) 47(-5.514,-3.421) 48(-5.514,-3.921)
  oval 0.3x1.8 smd: 17(3.786,5.379) 18(3.286,5.379) 19(2.786,5.379) 20(2.286,5.379) 21(1.786,5.379) 22(1.286,5.379) 23(0.786,5.379) 24(0.286,5.379) 25(-0.214,5.379) 26(-0.714,5.379) 27(-1.214,5.379) 28(-1.714,5.379) 29(-2.214,5.379) 30(-2.714,5.379) 31(-3.214,5.379) 32(-3.714,5.379) 49(-3.714,-5.721) 50(-3.214,-5.721) 51(-2.714,-5.721) 52(-2.214,-5.721) 53(-1.714,-5.721) 54(-1.214,-5.721) 55(-0.714,-5.721) 56(-0.214,-5.721) 57(0.286,-5.721) 58(0.786,-5.721) 59(1.286,-5.721) 60(1.786,-5.721) 61(2.286,-5.721) 62(2.786,-5.721) 63(3.286,-5.721) 64(3.786,-5.721)
  silkscreen extent -4.21,-4.75 5.71,4.08, body extent -4.96,-5.17 5.04,4.83, height 1.6
MSOP10 [mm]
  rect 1.2x0.25 smd: 1(-2.413,1.829) 2(-2.413,1.329) 3(-2.413,0.829) 4(-2.413,0.329) 5(-2.413,-0.171) 6(1.937,-0.171) 7(1.937,0.329) 8(1.937,0.829) 9(1.937,1.329) 10(1.937,1.829)
  silkscreen extent -1.27,-0.33 0.89,2.08
PSFM-T5 [mm]
  rect 1.5x1.2 hole 1: 1(0,0)
  oval 1.5x1.2 hole 1: 2(0,-1.7) 3(0,-3.4) 4(0,-5.1) 5(0,-6.8)
  silkscreen extent -1.95,-7.98 2.87,1.16
PWR_3T [mm]
  rect 3x3 hole 1.6: 1(0,0)
  round 3 hole 1.6: 2(0,-5) 3(0,-10)
  silkscreen extent -5,-12.67 5.05,3.3
Relay_OMRON5V [mm]
  rect 1.5x1.5 hole 0.7: 1(0,0)
  round 1.5 hole 0.8: 2(0,-2.54) 3(0,-10.16) 4(5.08,-10.16) 5(5.08,-2.54)
  round 1.5 hole 0.7: 6(5.08,0)
  silkscreen extent -1.5,-11.5 6.5,1.5
SMA [mm]
  round 2.2 hole 1.7: 1(2.55,-2.55) 2(0,-5.1) 2(0,0) 2(5.1,-5.1) 2(5.1,0)
SO-8N#1 [mm]
  rect 1.44x0.55 smd: 1(-4.013,3.302)
  oval 1.44x0.55 smd: 2(-4.013,2.022) 3(-4.013,0.742) 4(-4.013,-0.538) 5(1.487,-0.538) 6(1.487,0.742) 7(1.487,2.022) 8(1.487,3.302)
  silkscreen extent -2.46,-1.18 -0.07,3.94
SO-8N#2 [mm]
  rect 1.44x0.55 smd: 1(0,0)
  oval 1.44x0.55 smd: 2(0,-1.28) 3(0,-2.56) 4(0,-3.84) 5(5.5,-3.84) 6(5.5,-2.56) 7(5.5,-1.28) 8(5.5,0)
  silkscreen extent 1.55,-4.48 3.95,0.64
SOT23 [mm]
  rect 1.1x0.6 smd: 1(-1.325,1.001) 2(-1.325,-0.899) 3(1.275,0.051)
  silkscreen extent -1.75,-1.4 0.4,1.93
SOT-23-5 [mm]
  rect 0.6x1 smd: 1(-0.995,-1.101)
  oval 0.6x1 smd: 2(-0.045,-1.201) 3(0.905,-1.201) 4(0.905,1.499) 5(-0.995,1.499)
  silkscreen extent -0.4,1.5 0.4,1.5, body extent -1.5,-1.3 1.4,1.5, height 1.2
SOT_23 [mil]
  rect 36x36 smd: 1(0.28,-7.25)
  rect 36x30 smd: 2(0.28,67.75)
  rect 50x36 smd: 3(-79.72,30.75)
  silkscreen extent -85,-27 5,88
TestPoint [mm]
  round 1.6 hole 1: 1(-0.002,-0.002)
TO-220 [mm]
  rect 2x2.5 hole 1.3: 1(-2.565,0)
  oval 2x2.5 hole 1.3: 2(-0.025,0) 3(2.515,0)
  silkscreen extent -5.33,-2 5.27,2.8, body extent -5.11,-1.45 5.05,2.9, height 19.6
TSSOP16 [mm]
  rect 1.2x0.36 smd: 1(-0.021,-0.024)
  oval 1.2x0.36 smd: 2(-0.021,-0.664) 3(-0.021,-1.304) 4(-0.021,-1.944) 5(-0.021,-2.584) 6(-0.021,-3.224) 7(-0.021,-3.864) 8(-0.021,-4.504) 9(5.919,-4.504) 10(5.919,-3.864) 11(5.919,-3.224) 12(5.919,-2.584) 13(5.919,-1.944) 14(5.919,-1.304) 15(5.919,-0.664) 16(5.919,-0.024)
  silkscreen extent 1.41,-4.82 4.48,0.3
USB_A [mil] "USB A type Connector"
  round 60 hole 30: 1(-207.63,-180.91) 4(-207.63,94.09)
  oval 60x52.13 hole 30: 2(-207.63,-80.91) 3(-207.63,-0.91)
  oval 137.79x98.42 hole 78.74: 5(-87.63,239.09) 6(-87.63,-310.91)
  silkscreen extent -282,-341 357,264
USBmicro_B [mm]
  rect 0.4x1.6 smd: 1(1.542,-2.679) 2(0.892,-2.679) 3(0.242,-2.679) 4(-0.408,-2.679) 5(-1.058,-2.679)
  silkscreen extent -4.67,-3.56 5.12,1.93

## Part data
C1 C2 C3 C4 C5 C6 C7 C8 C9 C11 C12 C13 C14 C15 C17 C19 C20 C21 C22 C23 C29 C30 C31 C32 C33 C34 C35 C37 C39 C41 C43 C45 C47 C48 C49 C50 C58 C66 C70 C71 C72 C73 C74 C75 C76 C77 C78 C79 C80 C82 C83 C84 C90 C93 C94 C95 C101 C103 C105 C107 C108 C109 C120 C121 C122 C123 C124 C125 C150 C152 C154: library part Cap, "Capacitor"
C10 C16 C18 C38 C40 C42 C44 C46 C51 C52 C54 C55 C59 C60 C61 C67 C68 C97 C99 C100 C102 C104 C106 C151 C153 C156: library part "Cap Pol1", "Polarized Capacitor (Radial)"
C56 C57 C62 C81 C85: library part Cap, "Capacitor,100V"
D1 D2: library part "Diode 1N4007", "1 Amp General Purpose Rectifier"
D3 D4: "1 Amp General Purpose Rectifier"
FORCE_H FORCE_L GUARD SENSE_H SENSE_L: "SMB Straight Connector"
J1: library part "D Connector 9", "Receptacle Assembly, 9 Position, Right Angle"
K1 K2 K3 K4 K5 K6 K7 K8 K9 K10: library part "AXiCOM IM05"
K11 K12 K13 K14 K15: library part Relay_OMRON5V, "Relay OMRON"
L1 L2 L3: library part Inductor, "Inductor"
LCD: "Header, 8-Pin"
LED0 LED1: "Header, 2-Pin"
PWR_5V PWR_24V RS485_2: "Header, 3-Pin"
Q1 Q2 Q3 Q4 Q5 Q6 Q7 Q8 Q9 Q10 Q11 Q12 Q13 Q14 Q15: library part NUD3105, "Relay Driver 5V Supply"
R1 R2 R10 R12 R14 R16 R17 R18 R19 R21 R22 R23 R24 R25 R27 R28 R29 R30 R31 R32 R33 R34 R35 R36 R37 R38 R39 R40 R41 R42 R43 R44 R45 R46 R47 R49 R50 R51 R52 R53 R54 R55 R56 R57 R58 R59 R60 R61 R62 R66 R68 R69 R75 R76 R100 R101 R102 R103 R104 R105 R130 R131 R136 R137: library part Res1, "Resistor"
U1: library part STM32F103RBT6, "STM32 ARM-based 32-bit MCU with 128 Kbytes Flash, 64-pin LQFP, Industrial Temperature"
U3 U4: library part AD8676
U6 U7: library part AD8422
U12: "Ultralow Noise, XFET Voltage References"
U14: library part AD5687R
U17 U18: "AD8137ARZ"
U19 U20: library part AD8601, "Precision CMOS, Single Supply, Rail to Rail, Windband Operational Amplifiers"
USB: library part USB_Normal, "USB interface"

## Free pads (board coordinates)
  round 60 hole 30: 2(9652.86,5819.02)

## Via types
v1: diameter 30/30 (per signal layer), hole 14, Component Side to Solder Side, 662 vias
v2: diameter 50, hole 28, Component Side to Solder Side, 70 vias
v3: diameter 30, hole 14, Component Side to Solder Side, 26 vias
v4: diameter 39.37, hole 29.53, Component Side to Solder Side, 2 vias
v5: diameter 66.93, hole 47.24, Component Side to Solder Side, 2 vias

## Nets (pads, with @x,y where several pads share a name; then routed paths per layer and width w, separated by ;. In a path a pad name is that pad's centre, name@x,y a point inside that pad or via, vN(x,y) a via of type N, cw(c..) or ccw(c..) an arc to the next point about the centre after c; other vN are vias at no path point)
1.25V: U13.6 U13.7 U17.2 U18.2 | length 1791.2
  Component Side w10: U17.2@11254.04,6241.59 v1@11350.11,6241.59 ; U18.2@11260.38,7178.59 v1@11350.71,7178.59 ; v1@11351.73,5816.46 11351.73,5772.61 11417.9,5706.44 U13.7@11471.13,5706.44 U13.6@11471.13,5657.3
  Solder Side w10: v1@11350.95,7178.03 11351.26,7177.72 v1(11351.26,5813.12)
  other v1: 11349.85,6241.82 11350.39,7177.82
2.5V: C82.1 C83.1 R22.1 R61.1 U10.1 U10.2 U11.1 U11.2 U13.1 U13.2 | length 5904.5
  Component Side w10: v1@10686.34,7860.77 R22.1@10829.65,7860.77 ; v1(10690.86,7416.09) 11801.28,7416.09 v3@11885.8,7331.57 ; R61.1@11166.13,5707.19 U13.2@11253.05,5707.19 ; U13.2@11254.6,5707.26 U13.1@11254.6,5756.83 ; v3@11885.8,7332.77 12145.92,7332.77 C83.1@12202.28,7276.4 ; v1(11886.25,6372.07) 12137.93,6372.07 C82.1@12185.01,6324.99 ; C82.1@12214.45,6305.34 12258.6,6261.2 U10.2@12258.6,6110.3 ; C83.1@12214.94,7266.37 12262.02,7219.29 U11.1@12262.02,7085.81 U11.2@12262.02,7066.13
  Component Side w20: R61.1@11166.13,5707.19 11166.13,5514.38 11250.33,5430.18 v1@11884.37,5430.18 ; C82.1@12214.45,6305.34 C82.1@12214.45,6308.12
  Solder Side w10: v1@10689.5,7408.79 v1(10689.5,7862.85)
  Solder Side w20: v1@11886.2,5431.08 v3@11886.2,7331.93
  other v1: 11885.77,5430.03
  other v3: 11885.32,7334.06
5V: C9.2 C10.1 C11.2 C13.2 C60.1 C61.1 C62.2 C93.1 C94.2 C107.2 C120.2 C156.1 L2.1 PWR_5V.3 U12.2 U13.8 U14.5 U17.3 U18.3 U19.5 U20.5 | length 16199.3
  Component Side w10: U19.5@10681.14,6102.36 C107.2@10751.73,6102.36 ; U20.5@10684.1,7135.21 v3@10927.9,7135.21 ; C107.2@10756.23,6102.36 C107.2@10756.23,6104.13 ; v1@10926.35,5913.03 11437.3,5913.03 11471.97,5878.36 C94.2@11471.97,5831.65 ; U12.2@11252.61,5327.33 U12.2@11255.51,5324.42 ; U13.8@11471.14,5755.61 C94.2@11471.14,5833.08 ; U14.5@11987.2,7786.7 12055.02,7786.7 12097.01,7744.71 C9.2@12097.01,7629.59
  Component Side w20: C107.2@10754.08,6102.3 v1@10923.27,6102.3 ; v2(10926.27,5330.27) U12.2@11233.91,5330.27 ; v2@10926.51,7484.68 C10.1@12078.91,7484.68 ; v1@10926.89,6051.38 11327.33,6051.38 11343.84,6067.89 11343.84,6160.69 11313.37,6191.15 U17.3@11254.32,6191.15 ; v3@10928.44,6985.02 C13.2@11323.3,6985.02 ; U18.3@11263.82,7128.56 11299.04,7128.56 11332.07,7095.53 C13.2@11332.06,6986.12 ; C10.1@12095.39,7487.51 C9.2@12095.39,7627.9
  Component Side w40: v2@10929.36,10630.6 12556.01,10630.6 12786.52,10861.11 PWR_5V.3@12786.52,11751.73 C61.1@13277.32,11751.73
  Component Side w50: C61.1@13282.28,11746.73 C61.1@13286.74,11742.27
  Component Side w80: v2@13370.33,9583.76 13681.88,9272.2 L2.1@13681.88,9240.31
  Solder Side w30: v2@10925.09,5330.32 v2(10925.09,10632.31)
  Solder Side w40: v2(13681.88,9265.31) v2@13686.88,9260.31
  Solder Side w100: PWR_5V.3@12785.58,11752.26 12785.58,10168.59 v2@13682.88,9266.3
  other v1: 10924.91,5913.17 10924.09,6050.3 10923.79,6104.1
  other v2: 10925.46,7484.43 13628.41,9320.31 13566.88,9383.59 13506.88,9445.31 13440.52,9513.57 13373.78,9580.31
  other v3: 10928.19,6985.47 10926.5,7132.88
+15V: C15.2 C16.1 C19.2 C37.2 C38.1 C39.2 C40.1 C43.2 C44.1 C97.1 C100.1 C103.2 C104.1 C150.2 C151.1 D1.2 D3.1 K1.1 K2.1 K3.1 K4.1 K5.1 K6.1 K7.1 K8.1 K9.1 K10.1 K11.2 K12.2 K13.2 K14.2 K15.2 pad.2 R130.2 U2.5 U3.8 U4.8 U6.8 U7.8 U15.3 U23.8 | length 22871.1
  Component Side w10: C40.1@8332.25,9237.12 C40.1@8333.64,9237.12 ; C37.2@9711.82,9118.09 C37.2@9715.55,9118.09
  Component Side w20: U6.8@8333.64,8982.5 C40.1@8333.64,9237.12 ; K1.1@9715.55,8989.96 9715.55,9118.09 C38.1@9715.55,9255.12 ; C100.1@10324.81,9336.99 U4.8@10573.43,9336.99 ; U23.8@11279.24,7982.31 C151.1@11493.77,7982.31
  Component Side w30: K15.2@7912.65,9757.88 7912.65,9840.59 7956.35,9884.3 v2@8340.58,9884.3 ; v2@8339.14,10525.56 v2(9653.04,10525.56) ; U7.8@8339.58,7853.21 v2@8339.58,8186.31 ; C40.1@8340.06,9208.9 v2@8340.06,9317.74 ; v2@9652.06,10527.42 v2(10214.65,10527.42) v2@11977.45,10527.42 ; v2@9655.35,6519.15 K8.1@9715.55,6519.15 ; v2@9658.34,7931.04 K4.1@9715.55,7931.04 ; v2@9661.38,8284.01 K3.1@9715.55,8284.01 ; pad.2@9662.01,5813.21 K10.1@9715.55,5813.21 ; v2@9662.19,8636.98 K2.1@9715.55,8636.98 ; v2@9662.55,8989.96 K1.1@9715.55,8989.96 ; v2@9662.63,7578.07 K5.1@9715.55,7578.07 ; v2@9663,7225.1 K6.1@9715.55,7225.1 ; v2@9663.99,6872.13 K7.1@9715.55,6872.13 ; v2@9666.86,6166.18 K9.1@9715.55,6166.18 ; v2@10211.2,9332.99 C100.1@10328.77,9332.99 ; v2(10211.42,8913.88) v2@11034.08,8913.88 ; C151.1@11491.66,7970.77 v1@11977.18,7970.77 ; U2.5@11978.92,9782.7 C104.1@12229.19,9782.7 ; U3.8@11979.29,9188.23 v2(11979.29,9505.19)
  Component Side w40: D1.2@10161.84,11324.4 D3.1@10298.04,11324.4 ; v2@10215.11,10531.16 10215.11,11318.72 ; D3.1@10300.63,11324.13 R130.2@10300.63,11431.73
  Solder Side w10: K14.2@8016.68,6762.69 K14.2@8016.68,6769.26 ; v2@10213.02,10529.82 v2@10213.02,10533.35
  Solder Side w30: K13.2@8014.82,6387.86 7940.13,6387.86 7890.31,6437.68 7890.31,6726.27 7933.3,6769.26 8016.68,6769.26 8016.68,7169.78 8130.04,7283.14 8131.1,7283.14 8339.42,7491.45 v2(8339.42,9315.75) v2@8339.42,10524.6 ; pad.2@9652.86,5819.02 v2@9652.86,10531.52 ; v2@10213.06,8914.84 v2@10213.06,10533.38 ; K12.2@10633.32,8748.01 v2(10633.32,8911) ; K11.2@11038.89,8734.09 v2(11038.89,8914.84) ; v1@11978.92,7970.68 U2.5@11978.92,9782.7 ; U2.5@11979.55,9785.42 v2(11979.55,10532.44)
  other v1: 11979.24,7970.7
  other v2: 9658.64,6169.66 9650.76,6520.28 9655.15,6879.09 9652.82,7224.5 9658.64,7575.72 9652.82,7932.76 8341.77,8186.31 9652.82,8285.14 9655.15,8636.37 9651.66,8987.59 10211.2,9330.3 8342.85,9885.05 8339.14,10522.83
+24V: C66.1 C67.1 C68.1 D3.2 PWR_24V.3 R130.1 U15.1 | length 1229.6
  Component Side w40: PWR_24V.3@9927.23,11769.48 9928.53,11768.18 C68.1@10412.99,11768.18 ; U15.1@10412.06,11016.75 C68.1@10412.06,11760.01
-5V: C12.2 C14.2 C54.2 C55.2 C56.2 C95.2 C109.2 C121.2 PWR_5V.1 U13.4 U17.6 U18.6 U19.2 U20.2 | length 10332.2
  Component Side w10: U19.2@10644.62,6209.59 C109.2@10644.62,6288.07 10747.39,6288.07 v2@10833.19,6373.87 ; U20.2@10646.7,7241.51 C12.2@10646.7,7316.79 ; C12.2@10654.28,7326.78 10699.57,7372.07 v2(10834.15,7372.07) ; C95.2@11254.6,5532.61 U13.4@11254.6,5605.65 ; C95.2@11255.56,5529.52 11255.56,5493.48 11269.8,5479.24 v1@11518.76,5479.24
  Component Side w20: C14.2@11406.41,6987.33 11406.41,7111.24 11423.37,7128.2 U18.6@11476.92,7128.2 ; C14.2@11406.75,6986.06 v1@11519.82,6986.06 ; U17.6@11469.9,6192.76 11408.99,6192.76 11390.67,6174.45 11390.67,6078.97 C121.2@11421.67,6047.97 v1@11515.05,6047.97
  Component Side w40: v2@10829.92,6703.39 v2(11522.26,6703.39) ; v2@11521.4,10719.69 11775.58,10719.69 11878.93,10823.04 C54.2@11878.93,11746.73 ; C54.2@11883.88,11751.73 C56.2@12177.82,11751.73 PWR_5V.1@12392.82,11751.73
  Solder Side w30: v2@10835.13,6387.41 v2(10835.13,6697.59) v2@10835.13,7370.4 ; v1@11521.49,5483.9 v2(11521.49,10719.12)
  other v1: 11521.79,5481.46 11521.77,6047.71 11520.53,6986.57
  other v2: 10834.06,6372.77
-15V: C17.2 C18.2 C41.2 C42.2 C45.2 C46.2 C99.2 C101.2 C102.2 C105.2 C106.2 C152.2 C153.2 D2.1 D4.2 R27.1 R131.2 U2.3 U3.4 U4.4 U6.5 U7.5 U16.3 U23.4 | length 14178.1
  Component Side w10: R27.1@11705.95,9544.63 11705.95,9489.26 11763.4,9431.81 v1@11842.59,9431.81
  Component Side w20: C153.2@11062.71,7652.73 U23.4@11062.71,7831.13 ; U2.3@11845.06,9782.7 U2.3@11847.63,9785.27 ; v2(11848.57,8943.43) C18.2@11959.88,8943.43
  Component Side w30: v2@8178.14,8592.61 C42.2@8327.34,8592.61 ; v2@8185.8,7466.95 C46.2@8332.02,7466.95 ; C42.2@8333.64,8590.67 U6.5@8333.64,8831.32 ; C46.2@8339.58,7454.72 U7.5@8339.58,7694.16 ; U4.4@10789.97,9490.2 C102.2@10789.97,9719.91 ; C102.2@10794.81,9721.49 v2(10794.81,9846.65) ; C153.2@11063.88,7636.18 v1(11156.6,7636.18) ; C106.2@11472.48,9790.77 11596.45,9790.77 11674.55,9868.88 11812.85,9868.88 11845.06,9836.67 U2.3@11845.06,9782.7 ; C17.2@11763.07,8941.32 U3.4@11763.07,9022.53 ; C17.2@11766.68,8943.43 v2(11848.57,8943.43)
  Component Side w40: v2@8180.86,10150.13 8181.09,10150.36 v2(8920.12,10150.36) 11841.99,10150.36 v2@11842.22,10150.13 ; D2.1@8798.46,11346.47 D4.2@8921.74,11346.47 ; D4.2@8920.05,11353.51 R131.2@8920.05,11461.48 ; U16.3@8922.53,11015.51 D4.2@8922.53,11329.05
  Component Side w50: v2@8922.53,10651.2 U16.3@8922.53,11015.51
  Solder Side w30: v2@8183.55,7465.95 v2@8183.55,10149.75 ; v1@11155.5,7637.77 11207.99,7690.26 v2(11207.99,10147.78) ; v2@11845.06,8941.43 U2.3@11845.06,9782.7 v2@11845.06,10152.88
  Solder Side w40: v2@8921.22,10149.01 v2@8924.24,10145.99 ; v2(10794.81,9846.65) v2@10794.81,10149.32
  Solder Side w50: v2@8921.22,10149.01 v2(8921.22,10654.92)
  other v1: 11844.8,9429.11
  other v2: 8184.02,7466.45 8183.55,8594.88 8183.55,10148.7 10794.48,10150.37 11844.64,10150.16
-24V: C50.1 C51.2 C52.2 D4.1 PWR_24V.1 R131.1 U16.2 | length 1205.7
  Component Side w40: U16.2@9027.12,11013.64 9027.12,11761.91 C52.2@9029.64,11764.43 ; C52.2@9034.69,11764.48 C50.1@9323.53,11764.48 PWR_24V.1@9488.53,11764.48
ADC1_CNV: U1.38 U10.6 | length 1502.4
  Component Side w10: U10.6@12417.28,6046.61 13483.44,6046.61 13639.4,6202.57 U1.38@13639.4,6418.24
ADC1_SCK: U1.36 U10.8 | length 1418.3
  Component Side w10: U10.8@12413.91,6086.26 13429.6,6086.26 13600.03,6256.69 U1.36@13600.03,6418.24
ADC1_SDI: U1.35 U10.9 | length 1379.5
  Component Side w10: U10.9@12415.88,6105.86 13413.58,6105.86 13580.34,6272.62 U1.35@13580.34,6418.24 ; U10.9@12427.91,6106.09 U10.9@12428.13,6105.86
ADC1_SDO: U1.37 U10.7 | length 1462.2
  Component Side w10: U10.7@12415.6,6066.35 13459.55,6066.35 13619.71,6226.51 U1.37@13619.71,6418.24
ADC2_CNV: U1.23 U11.6 | length 1246.3
  Component Side w10: U11.6@12434.24,7006.8 12546.08,7006.8 12594.56,6958.32 12594.56,6839.93 12768.22,6666.27 U1.23@13470.11,6666.27
ADC2_SCK: U1.21 U11.8 | length 1265.3
  Component Side w10: U11.8@12419.97,7046.14 12582.11,7046.14 12644.86,6983.39 12644.86,6856.91 12796.13,6705.64 U1.21@13470.11,6705.64
ADC2_SDI: U1.20 U11.9 | length 1266
  Component Side w10: U11.9@12421.61,7065.74 12597.81,7065.74 12671.13,6992.42 12671.13,6861.85 12807.66,6725.33 U1.20@13470.11,6725.33
ADC2_SDO: U1.22 U11.7 | length 1258.5
  Component Side w10: U11.7@12423.29,7026.36 12561.51,7026.36 12619.58,6968.29 12619.58,6847.66 12781.29,6685.96 U1.22@13470.11,6685.96
AGND: C7.2 C8.2 C9.1 C10.2 C11.1 C12.1 C13.1 C14.1 C15.1 C16.2 C17.1 C18.1 C19.1 C20.1 C21.2 C31.1 C32.2 C33.1 C35.2 C37.1 C38.2 C39.1 C40.2 C41.1 C42.1 C43.1 C44.2 C45.1 C46.1 C47.2 C48.2 C49.2 C50.2 C51.1 C52.1 C54.1 C55.1 C56.1 C60.2 C61.2 C62.1 C66.2 C67.2 C68.2 C80.2 C82.2 C83.2 C84.1 C90.1 C93.2 C94.1 C95.1 C97.2 C99.1 C100.2 C101.1 C102.1 C103.1 C104.2 C105.1 C106.1 C107.1 C109.1 C120.1 C121.1 C150.1 C151.2 C152.1 C153.1 C156.2 D1.1 D2.2 FORCE_L.1 FORCE_L.2 GUARD.2 K15.1 L3.1 PWR_5V.2 PWR_24V.2 Q1.2 Q2.2 Q3.2 Q4.2 Q5.2 Q6.2 Q7.2 Q8.2 Q9.2 Q10.2 Q11.2 Q12.2 Q13.2 Q14.2 Q15.2 R17.2 R23.1 R55.1 R59.2 R62.2 R75.2 S1.2 S2.2 S3.2 S4.2 SENSE_L.2 T5.1 U6.6 U7.6 U10.5 U11.5 U12.4 U14.4 U14.9 U14.16 U15.2 U16.1 U23.5 | length 2734.6
  Component Side w10: FORCE_L.1@7295.38,5772.23 R75.2@7295.38,6324.21 ; 9659.47,11707.46 PWR_24V.2@9722.05,11770.04 9789.51,11837.49 ; v1@10529.48,7320.29 C12.1@10583.55,7320.29 ; S2.2@10583.07,6049.93 10672.62,6049.93 ; C107.1@10753.96,6163 10833.65,6163 ; v1@11026.28,6289.84 R55.1@11092.27,6289.84 ; 11058.16,7228.92 R59.2@11103.79,7228.92 ; 11102.64,5423.76 11136.34,5390.06 C93.2@11168.28,5390.06 ; 11240.83,5987.79 C120.1@11283.41,5987.79 ; C95.1@11318.56,5529.52 v1@11401.44,5529.52 ; 11332.06,6877.33 C13.1@11332.06,6923.12 ; C94.1@11408.98,5831.65 v1@11408.98,5878.33 ; C121.1@11421.67,5984.98 11465.23,5984.98 ; C90.1@11570.27,5217.85 11613.52,5217.85 ; 11797.51,7812.12 C48.2@11838.5,7812.12 ; C20.1@11854.33,9544.72 11913.81,9544.72 ; U14.4@11987.2,7811.9 v1@12087.01,7811.9 ; 12060,5982.42 C7.2@12099.37,5982.42 12099.37,5941.25 ; 12059.99,6947.52 C8.2@12098.14,6947.52 12098.14,6912.47 ; 12167.82,7727.43 12184.14,7711.11 U14.9@12221.05,7711.11 12284.26,7711.11 ; 12527.88,11811.66 12652.32,11687.22
  Component Side w20: Q12.2@10608.97,8518.3 10655.43,8518.3 ; Q11.2@11010.66,8518.87 11061.63,8518.87
  Component Side w30: v1@9853.57,8508.48 Q2.2@9925.34,8436.71 ; v1(9854.12,8510.12) v1@9854.12,8573.39
  Solder Side w10: 9659.47,11832.62 PWR_24V.2@9722.05,11770.04 9739.58,11770.04 9802.37,11707.25 ; 12522.82,11696.73 12642.47,11816.39
  other v1: 9119.58,4937.76 9199.58,4937.76 9279.58,4937.76 8083.71,5222.19 7944.46,5225.97 9513.32,5235.77 9593.32,5235.77 9673.32,5235.77 12253.2,5249.04 8760.21,5250.71 8844.7,5250.56 12113.94,5252.82 8083.71,5302.19 7944.46,5305.97 10709.68,5311.57 10789.68,5311.57 9513.32,5315.77 9593.32,5315.77 9673.32,5315.77 12253.2,5329.04 8760.21,5330.71 8844.7,5330.56 12113.94,5332.82 7204.06,5373.16 7284.06,5373.16 7364.06,5373.16 8083.71,5382.19 7944.46,5385.97 10709.68,5391.57 10789.68,5391.57 12253.2,5409.04 8760.21,5410.71 8844.7,5410.56 12113.94,5412.82 7204.06,5453.16 7284.06,5453.16 7364.06,5453.16 10709.68,5471.57 10789.68,5471.57 11403.1,5529.69 12122.11,5630.79 8087.66,5656.21 11691.65,5680.35 11771.65,5680.35 12122.11,5710.79 8087.66,5736.21 11691.65,5760.35 11771.65,5760.35 9860.3,5767.35 9940.3,5767.35 12122.11,5790.79 8087.66,5816.21 11691.65,5840.35 11771.65,5840.35 11409.15,5882.35 11013.58,5979.59 11093.58,5979.59 11173.58,5979.59 9844.47,6109.95 9924.47,6109.95 10430.13,6131.68 10344.25,6133.43 10189.45,6147.97 10862.42,6165.36 8234.43,6196.24 8314.43,6196.24 8394.43,6196.24 12005.55,6220.58 10189.45,6227.97 10862.42,6245.36 7195.26,6268.67 11023.82,6289.7 10495.81,6296.27 12005.55,6300.58 10189.45,6307.97 7195.26,6348.67 10716.66,6356.41 10495.81,6376.27 7195.26,6428.67 9850.85,6441.38 9930.85,6441.38 8250.75,6604.33 8330.75,6604.33 8410.75,6604.33 10185.39,6714.24 10265.39,6714.24 11669.9,6724.27 11749.9,6724.27 12103.15,6747.81 12183.15,6747.81 9851.08,6792.01 9931.08,6792.01 10185.39,6794.24 10265.39,6794.24 11669.9,6804.27 11749.9,6804.27 11088.22,6811.19 11168.22,6811.19 12103.15,6827.81 12183.15,6827.81 7909.39,6862.93 10185.39,6874.24 10265.39,6874.24 11669.9,6884.27 11749.9,6884.27 11088.22,6891.19 11168.22,6891.19 7909.39,6942.93 8256.22,6961.34 8116.96,6965.12 7909.39,7022.93 8256.22,7041.34 8116.96,7045.12 11010.3,7055.64 10376.85,7112.32 8256.22,7121.34 8116.96,7125.12 9838.42,7154.71 9918.42,7154.71 11996.47,7178.01 10376.85,7192.32 11996.47,7258.01 10763.58,7268.17 11250.9,7281.32 11330.9,7281.32 11410.9,7281.32 10524.43,7320.28 12109.82,7388.63 12189.82,7388.63 12269.82,7388.63 7215.39,7453.44 7354.65,7453.89 9850.7,7513.37 9930.7,7513.37 7215.39,7533.44 7354.65,7533.89 11672.78,7551.96 11752.78,7551.96 11832.78,7551.96 7215.39,7613.44 7354.65,7613.89 11833.76,7622.04 11375.08,7648.29 10286.43,7710.22 10147.17,7714 11375.08,7728.29 10521.64,7781.02 10286.43,7790.22 10147.17,7794 11375.08,7808.29 12083.42,7811.72 9851.42,7861.04 9931.42,7861.04 10521.64,7861.02 11646.65,7867.13 11726.65,7867.13 10286.43,7870.22 10147.17,7874 10521.64,7941.02 12159.82,8065.81 12239.82,8065.81 11696.71,8072.56 11776.71,8072.56 11856.71,8072.56 10734.81,8074.25 10814.81,8074.25 12159.82,8145.81 12239.82,8145.81 11696.71,8152.56 11776.71,8152.56 11856.71,8152.56 10734.81,8154.25 10814.81,8154.25 9859.68,8215.68 9939.68,8215.68 10162.1,8417.34 10267.26,8418.92 9893.9,8468.28 10741.99,8486.78 10162.1,8497.34 10267.26,8498.92 11301,8534.98 10741.99,8566.78 9853.9,8572.95 10162.1,8577.34 10267.26,8578.92 11682.43,8596.1 11762.43,8596.1 11842.43,8596.1 11301,8614.98 10741.99,8646.78 11682.43,8676.1 11762.43,8676.1 11842.43,8676.1 11301,8694.98 10741.99,8726.78 11301,8774.98 10543.2,8832.53 11301,8854.98 9851.42,8928.82 9924.07,8928.82 10740.72,8993.09 8734.89,9000.17 8819.39,9000.02 10740.72,9073.09 12140.5,9078.01 12220.5,9078.01 8734.89,9080.17 8819.39,9080.02 9373.27,9124.47 9885.68,9128.32 9965.68,9128.32 10463.73,9137.38 10553.49,9139.87 12140.5,9158.01 12220.5,9158.01 8734.89,9160.17 8819.39,9160.02 10702.49,9169.43 9373.27,9204.47 7690.84,9206.95 7770.84,9206.95 9885.68,9208.32 9965.68,9208.32 11289.56,9235.2 11369.56,9235.2 11449.56,9235.2 10702.49,9249.43 10992.24,9285.66 11072.24,9285.66 7690.84,9286.95 7770.84,9286.95 9885.68,9288.32 9965.68,9288.32 11610.95,9355.01 7690.84,9366.95 7770.84,9366.95 11610.95,9435.01 11610.95,9515.01 11024.72,9593.29 11610.95,9595.01 11024.72,9673.29 11024.72,9753.29 10489.87,9770.27 10350.61,9774.06 9350.58,9786.81 9430.58,9786.81 9510.58,9786.81 9926.81,9804.01 10011.31,9803.87 12686.6,9807.38 12547.35,9811.16 10489.87,9850.27 10350.61,9854.06 7364.03,9883.99 9926.81,9884.01 10011.31,9883.87 7212.47,9885.9 12686.6,9887.38 12547.35,9891.16 9354.37,9926.07 9434.37,9926.07 9514.37,9926.07 10489.87,9930.27 10350.61,9934.06 7364.03,9963.99 7212.47,9965.9 12686.6,9967.38 12547.35,9971.16 14276.88,9990.31 14356.88,9990.31 14436.88,9990.31 7364.03,10043.99 7212.47,10045.9 14276.88,10070.31 14356.88,10070.31 14436.88,10070.31 7609.89,10102.6 7689.89,10102.6 7609.89,10182.6 7689.89,10182.6 7609.89,10262.6 7689.89,10262.6 15458.97,10461.71 15538.97,10461.71 15458.97,10541.71 15538.97,10541.71 15458.97,10621.71 15538.97,10621.71 13581.88,10635.31 13661.88,10635.31 14261.46,10702.8 14341.46,10702.8 14421.46,10702.8 13581.88,10715.31 13661.88,10715.31 9621.89,10768.75 9482.63,10772.53 14261.46,10782.8 14341.46,10782.8 14421.46,10782.8 9621.89,10848.75 9482.63,10852.53 8386.95,10857.01 8466.95,10857.01 8546.95,10857.01 14261.46,10862.8 14341.46,10862.8 14421.46,10862.8 9621.89,10928.75 9482.63,10932.53 8386.95,10937.01 8466.95,10937.01 8546.95,10937.01 8386.95,11017.01 8466.95,11017.01 8546.95,11017.01 13095.51,11050.26 12956.26,11054.04 12255.55,11100.39 12335.55,11100.39 12415.55,11100.39 12495.55,11100.39 13095.51,11130.26 12956.26,11134.04 12255.55,11180.39 12335.55,11180.39 12415.55,11180.39 12495.55,11180.39 11072.72,11180.82 11152.72,11180.82 11232.72,11180.82 8242.34,11188.43 8103.08,11192.21 13095.51,11210.26 12956.26,11214.04 9615.98,11236.33 9695.98,11236.33 9775.98,11236.33 15005.51,11254.49 15085.51,11254.49 15165.51,11254.49 15245.51,11254.49 11072.72,11260.82 11152.72,11260.82 11232.72,11260.82 8242.34,11268.43 8103.08,11272.21 9615.98,11316.33 9695.98,11316.33 9775.98,11316.33 15005.51,11334.49 15085.51,11334.49 15165.51,11334.49 15245.51,11334.49 11072.72,11340.82 11152.72,11340.82 11232.72,11340.82 8242.34,11348.43 8103.08,11352.21 9615.98,11396.33 9695.98,11396.33 9775.98,11396.33 15005.51,11414.49 15085.51,11414.49 15165.51,11414.49 15245.51,11414.49 12487.82,11506.73 12567.82,11506.73 12647.82,11506.73 12487.82,11586.73 12567.82,11586.73 12647.82,11586.73 9653.53,11629.48 9733.53,11629.48 9813.53,11629.48 11210.94,11680.83 11290.94,11680.83 11370.94,11680.83 8150.5,11683.78 8230.5,11683.78 8310.5,11683.78 11210.94,11760.83 11290.94,11760.83 11370.94,11760.83 8150.5,11763.78 8230.5,11763.78 8310.5,11763.78 14213.96,11902.57 14293.96,11902.57 14373.96,11902.57 14453.96,11902.57 7752.74,11903.76 7832.74,11903.76 7912.74,11903.76 7992.74,11903.76 14213.96,11982.57 14293.96,11982.57 14373.96,11982.57 14453.96,11982.57 7752.74,11983.76 7832.74,11983.76 7912.74,11983.76 7992.74,11983.76 14213.96,12062.57 14293.96,12062.57 14373.96,12062.57 14453.96,12062.57 7752.74,12063.76 7832.74,12063.76 7912.74,12063.76 7992.74,12063.76
CTRL1: Q1.1 U1.8 | length 5256.8
  Component Side w10: Q1.1@9925.34,8714.79 9925.34,8528.76 10110.95,8343.15 13242.41,8343.15 13698.45,7887.1 U1.8@13698.45,6855.25
CTRL2: Q2.1 U1.9 | length 4950.9
  Component Side w10: Q2.1@9925.34,8361.71 9968.09,8361.71 10020.2,8309.6 13203.48,8309.6 13678.77,7834.31 U1.9@13678.77,6855.25
CTRL3: Q3.1 U1.10 | length 4976.8
  Component Side w10: Q3.1@9925.34,8008.63 9980.41,8008.63 10247.71,8275.92 13166.89,8275.92 13659.08,7783.73 U1.10@13659.08,6855.25
CTRL4: Q4.1 U1.11 | length 5216.6
  Component Side w10: Q4.1@9925.34,7655.54 9975.56,7655.54 10017.06,7697.04 10017.06,7994.24 10263.87,8241.05 13127.39,8241.05 13639.4,7729.04 U1.11@13639.4,6855.25
CTRL5: Q5.1 U1.24 | length 4176.1
  Component Side w10: Q5.1@9913.04,7312.61 Q5.1@9925.92,7299.73 ; Q5.1@9923.35,7301.01 10007.18,7301.01 10064.93,7243.25 10064.93,6717.16 10173.98,6608.12 12136.1,6608.12 12174.57,6646.59 U1.24@13470.11,6646.59
CTRL6: Q6.1 U1.25 | length 3815.2
  Component Side w10: Q6.1@9933.68,6942.7 10026.35,6850.03 10026.35,6669.81 10120.48,6575.67 12140.06,6575.67 12191.29,6626.9 U1.25@13470.11,6626.9
CTRL7: Q7.1 U1.26 | length 3593.2
  Component Side w10: Q7.1@9924.31,6593.69 9929.44,6593.69 9979.91,6543.22 12151.86,6543.22 12211.24,6602.6 12212.32,6602.6 12216.93,6607.22 U1.26@13470.11,6607.22
CTRL8: Q8.1 U1.27 | length 3767.3
  Component Side w10: Q8.1@9926.98,6242.79 9975.43,6242.79 10010.22,6277.58 10010.22,6416.52 10106.13,6512.43 12162.72,6512.43 12237.82,6587.53 U1.27@13470.11,6587.53
CTRL9: Q9.1 U1.28 | length 4095
  Component Side w10: Q9.1@9922.68,5889.82 10002.73,5889.82 10060.66,5947.75 10060.66,6403.01 10135.97,6478.32 12178.79,6478.32 12268.32,6567.85 U1.28@13470.11,6567.85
